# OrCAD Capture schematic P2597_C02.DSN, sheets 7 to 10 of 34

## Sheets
7 27_DC Jack: size Custom
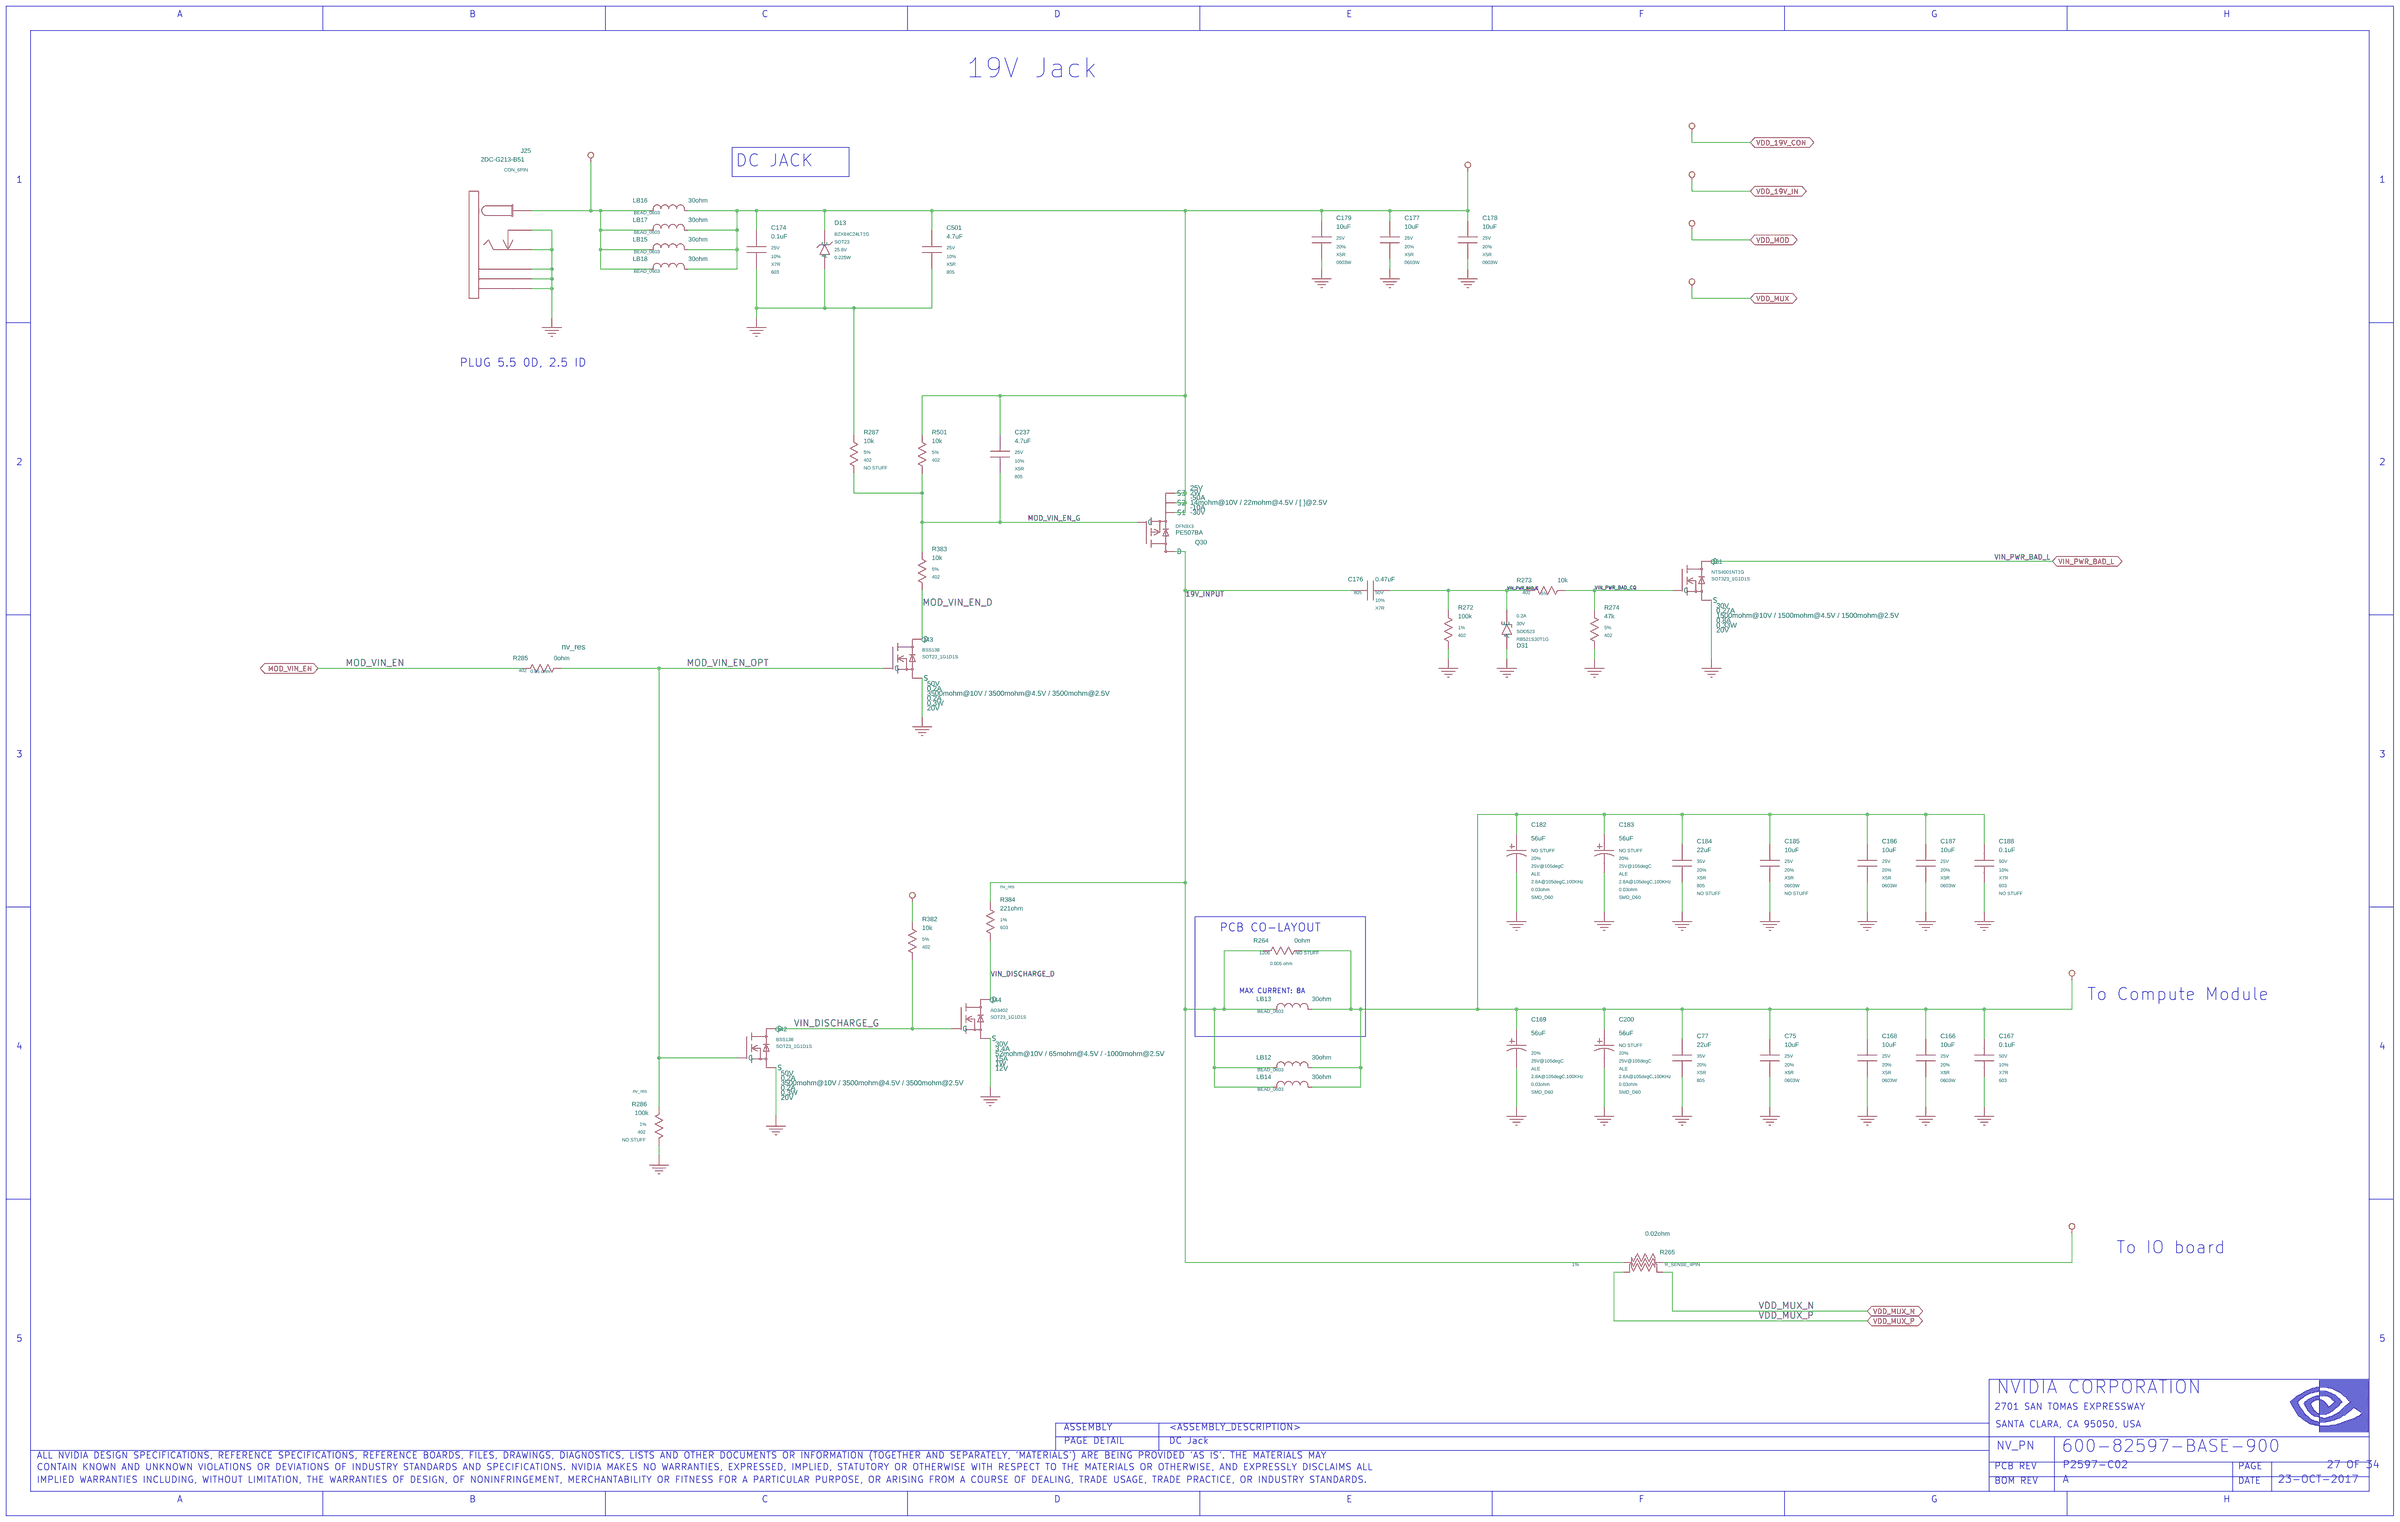
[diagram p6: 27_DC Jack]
8 26_BLANK
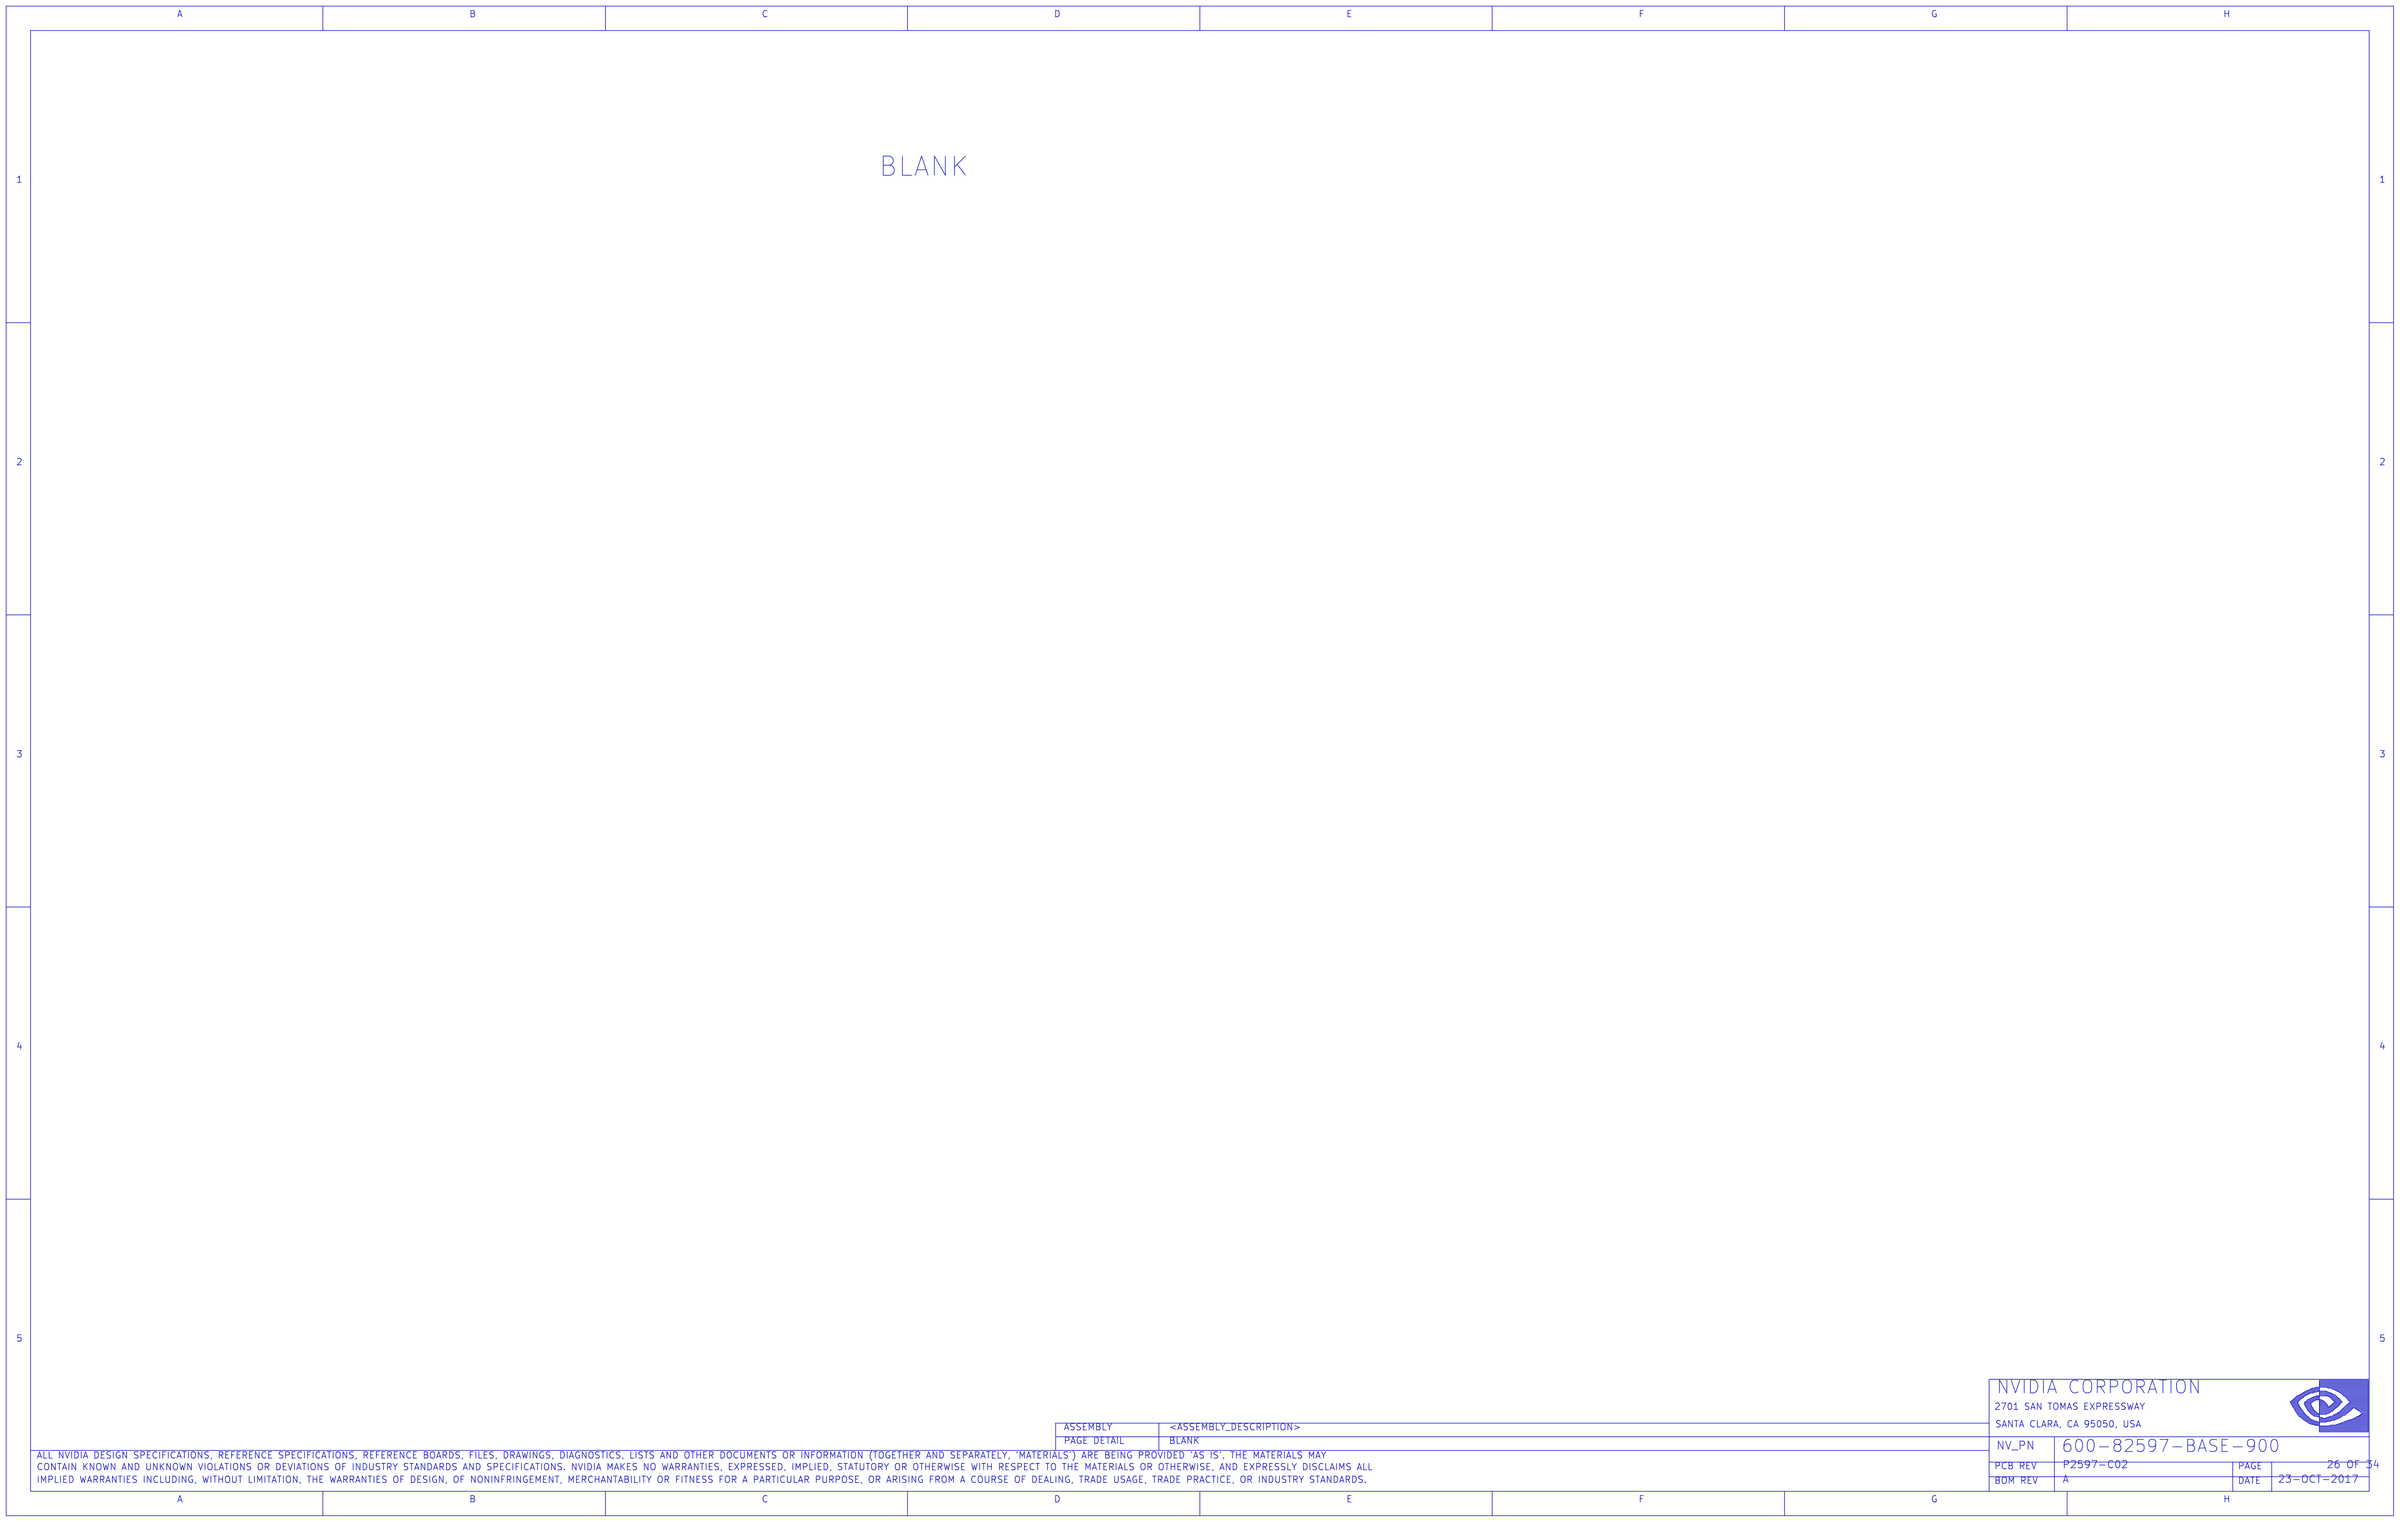
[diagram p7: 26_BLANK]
9 25_Supervisor: size Custom
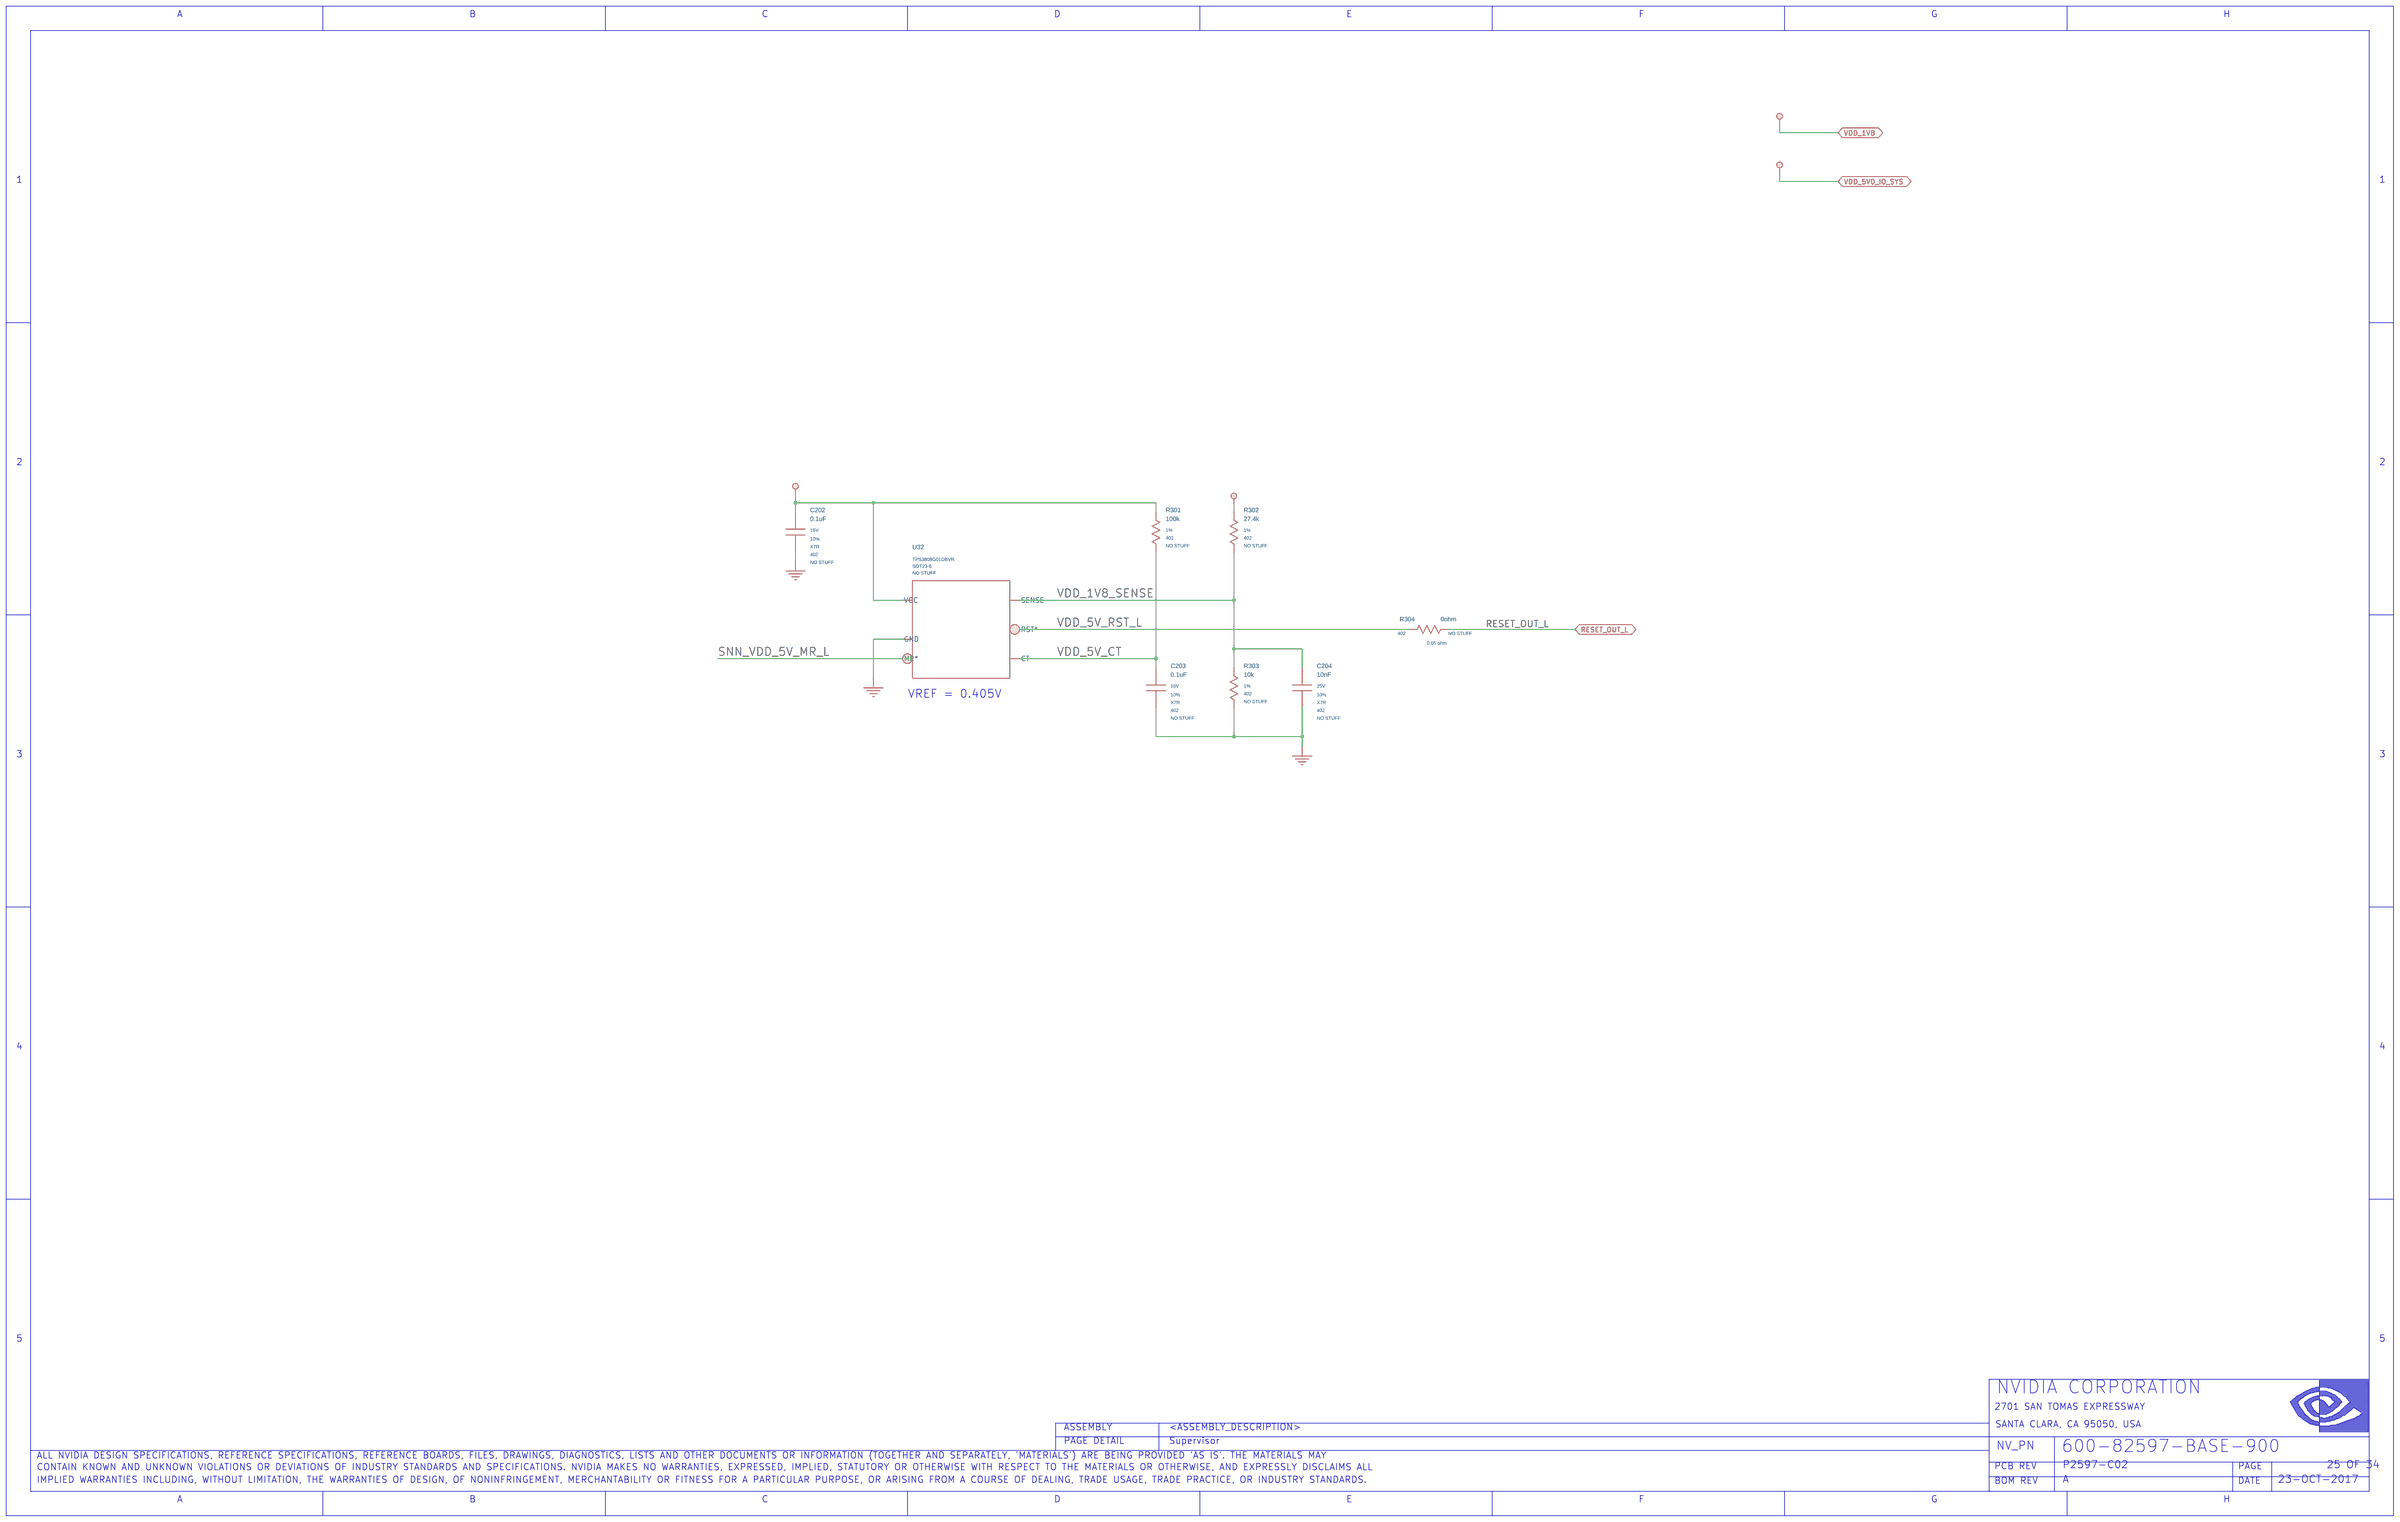
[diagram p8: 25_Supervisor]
10 24_EEPROM: size Custom
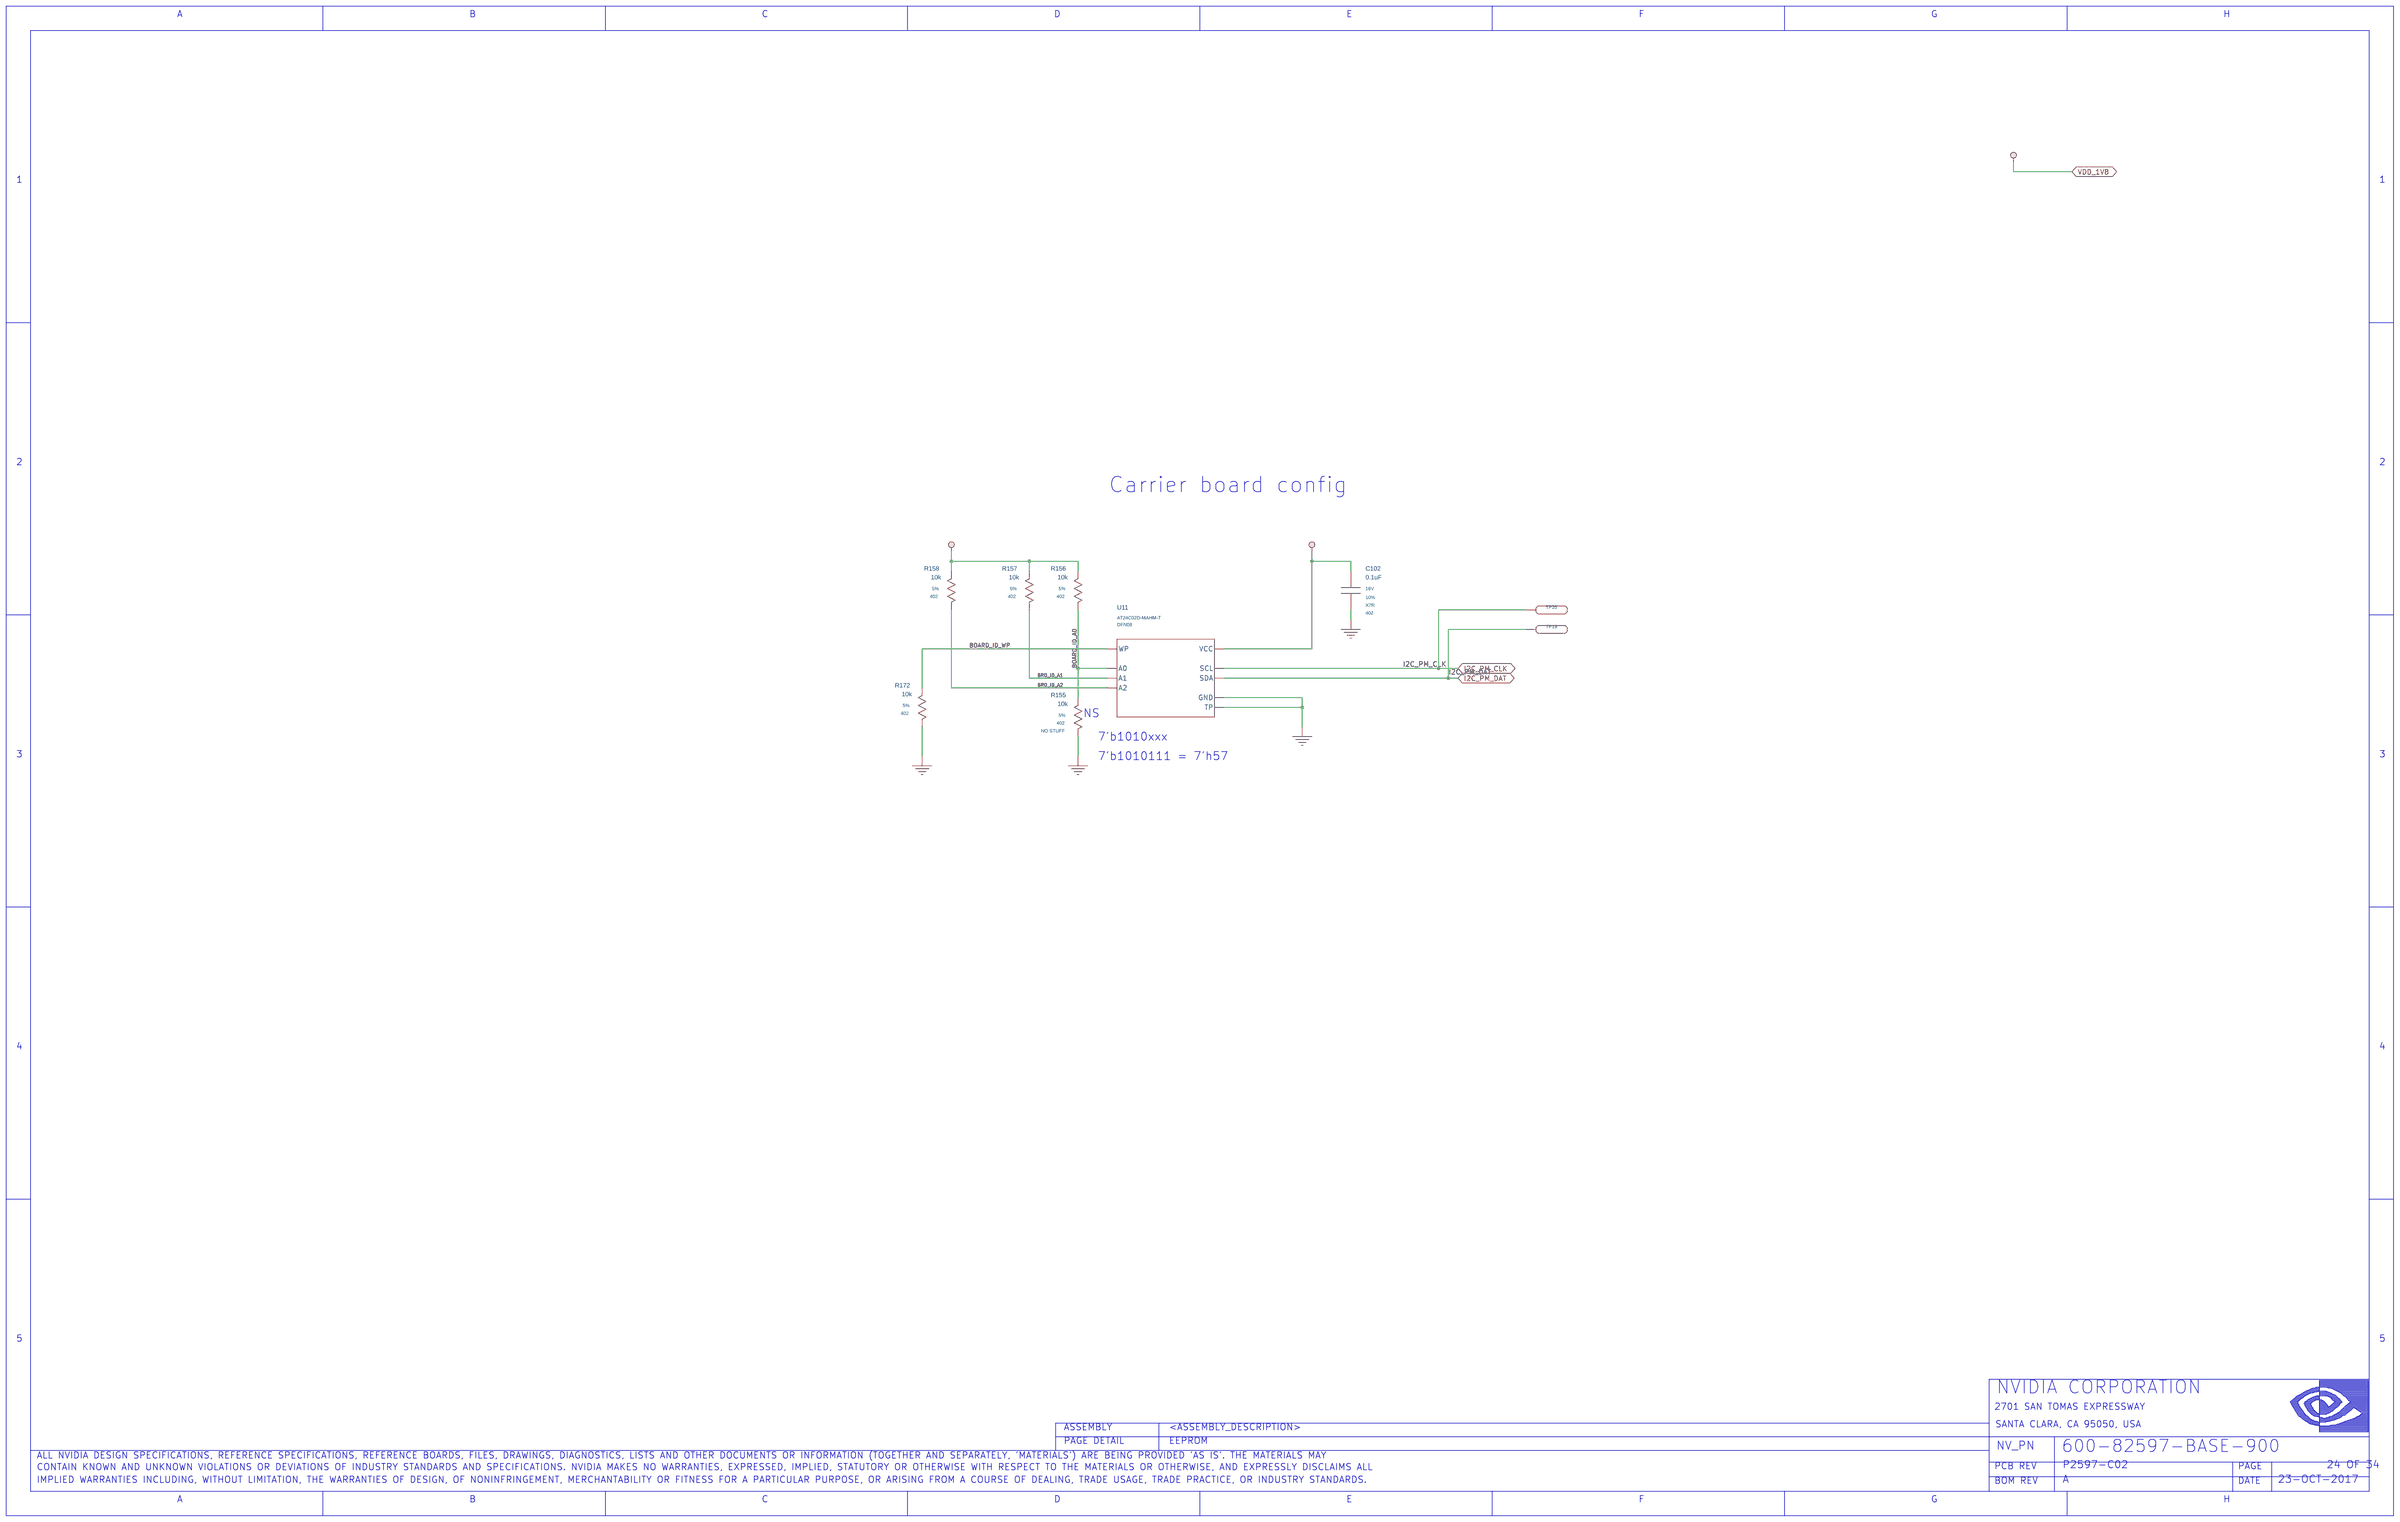
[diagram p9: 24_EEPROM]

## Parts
sheet 24_EEPROM
C102  0.1uF  [402]
R155  10k  [402]
R156  10k  [402]
R157  10k  [402]
R158  10k  [402]
R172  10k  [402]
TP19  LABTESTPOINT  [LTPT28C49P]
TP20  LABTESTPOINT  [LTPT28C49P]
U11  U_MEM_EE_I2C  [DFN08_P050_030X020_T016X016]
sheet 25_Supervisor
C202  0.1uF  [402]
C203  0.1uF  [402]
C204  10nF  [402]
R301  100k  [402]
R302  27.4k  [402]
R303  10k  [402]
R304  0ohm  [402]
U32  U_RST_TPS3808  [SOT23_6]
sheet 27_DC Jack
C75  10uF  [0603_LARGE]
C77  22uF  [805]
C166  10uF  [0603_LARGE]
C167  0.1uF  [603]
C168  10uF  [0603_LARGE]
C169  56uF  [CAP_SMD_066X066]
C174  0.1uF  [603]
C176  0.47uF  [805]
C177  10uF  [0603_LARGE]
C178  10uF  [0603_LARGE]
C179  10uF  [0603_LARGE]
C182  56uF  [CAP_SMD_066X066]
C183  56uF  [CAP_SMD_066X066]
C184  22uF  [805]
C185  10uF  [0603_LARGE]
C186  10uF  [0603_LARGE]
C187  10uF  [0603_LARGE]
C188  0.1uF  [603]
C200  56uF  [CAP_SMD_066X066]
C237  4.7uF  [805]
C501  4.7uF  [805]
D13  D_ZENER  [SOT23]
D31  D_SCHOTTKY  [DIODE_SMD_SOD523_B]
J25  CON_PWR_JACK  [CON_DCPWR_JACK_006_TH_RA_100X130]
LB12  30ohm  [IND_SMD_0603]
LB13  30ohm  [IND_SMD_0603]
LB14  30ohm  [IND_SMD_0603]
LB15  30ohm  [IND_SMD_0603]
LB16  30ohm  [IND_SMD_0603]
LB17  30ohm  [IND_SMD_0603]
LB18  30ohm  [IND_SMD_0603]
Q30  Q_FET_P_ENH  [DFET_SMD_032X033]
Q31  Q_FET_N_ENH  [SOT323]
Q42  Q_FET_N_ENH  [SOT23]
Q43  Q_FET_N_ENH  [SOT23]
Q44  Q_FET_N_ENH  [SOT23]
R264  0ohm  [1206]
R265  0.02ohm  [RES_04_SMD_32X016_B]
R272  100k  [402]
R273  10k  [402]
R274  47k  [402]
R285  0ohm  [402]
R286  100k  [402]
R287  10k  [402]
R382  10k  [402]
R383  10k  [402]
R384  221ohm  [603]
R501  10k  [402]

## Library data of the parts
C102 = C: ASSEMBLY: L4T_EEPROM; CDS_LIB: discrete; CDS_PART_NAME: C_0402-0.1UF,X7R,10%,16V,036-0014-000; CDS_PHYS_PART_NAME: C_0402-0.1UF,X7R,10%,16V,036-0014-000-0.1UF,036-0014-000; CDS_SEC: 1; DEVICE_TYPENAME: C_0402-01UFX7R1016V036-0014-000-01UF036-0014-000; DRAWING: @P2597_C02_LIB.P2597_C02(SCH_1):PAGE24; MAT: X7R; MAX_VOLTAGE: 16V; NV_PN: 036-0014-000; PATH: I34; PHYS_PAGE: 24; ROT: 0; SEC: 1; SIGNAL_MODEL: nv_cap; TOL: 10%; VER: 1; XY: (-5250,4600)
R155 = R#1: ASSEMBLY: L4T_EEPROM; CDS_LIB: discrete; CDS_PART_NAME: R_0402-10K,5 %,62.5MW,195-0486-000; CDS_PHYS_PART_NAME: R_0402-10K,5 %,62.5MW,195-0486-000-10K,195-0486-000; CDS_SEC: 1; CHIPS_PART_NAME: R; DEVICE_TYPENAME: R_0402-10K5625MW195-0486-000-10K195-0486-000; DRAWING: @P2597_C02_LIB.P2597_C02(SCH_1):PAGE24; MAX_WATTAGE: 62.5mW; NV_PN: 195-0486-000; PATH: I43; PHYS_PAGE: 24; ROT: 2; SEC: 1; SIGNAL_MODEL: nv_res; SKU: NO STUFF; TOL: 5%; VER: 2; XY: (-6650,3950)
R156 = R#1: ASSEMBLY: L4T_EEPROM; CDS_LIB: discrete; CDS_PART_NAME: R_0402-10K,5 %,62.5MW,195-0486-000; CDS_PHYS_PART_NAME: R_0402-10K,5 %,62.5MW,195-0486-000-10K,195-0486-000; CDS_SEC: 1; CHIPS_PART_NAME: R; DEVICE_TYPENAME: R_0402-10K5625MW195-0486-000-10K195-0486-000; DRAWING: @P2597_C02_LIB.P2597_C02(SCH_1):PAGE24; MAX_WATTAGE: 62.5mW; NV_PN: 195-0486-000; PATH: I32; PHYS_PAGE: 24; ROT: 2; SEC: 1; SIGNAL_MODEL: nv_res; TOL: 5%; VER: 2; XY: (-6650,4600)
R157 = R#1: ASSEMBLY: L4T_EEPROM; CDS_LIB: discrete; CDS_PART_NAME: R_0402-10K,5 %,62.5MW,195-0486-000; CDS_PHYS_PART_NAME: R_0402-10K,5 %,62.5MW,195-0486-000-10K,195-0486-000; CDS_SEC: 1; CHIPS_PART_NAME: R; DEVICE_TYPENAME: R_0402-10K5625MW195-0486-000-10K195-0486-000; DRAWING: @P2597_C02_LIB.P2597_C02(SCH_1):PAGE24; MAX_WATTAGE: 62.5mW; NV_PN: 195-0486-000; PATH: I31; PHYS_PAGE: 24; ROT: 2; SEC: 1; SIGNAL_MODEL: nv_res; TOL: 5%; VER: 2; XY: (-6900,4600)
R158 = R#1: ASSEMBLY: L4T_EEPROM; CDS_LIB: discrete; CDS_PART_NAME: R_0402-10K,5 %,62.5MW,195-0486-000; CDS_PHYS_PART_NAME: R_0402-10K,5 %,62.5MW,195-0486-000-10K,195-0486-000; CDS_SEC: 1; CHIPS_PART_NAME: R; DEVICE_TYPENAME: R_0402-10K5625MW195-0486-000-10K195-0486-000; DRAWING: @P2597_C02_LIB.P2597_C02(SCH_1):PAGE24; MAX_WATTAGE: 62.5mW; NV_PN: 195-0486-000; PATH: I29; PHYS_PAGE: 24; ROT: 2; SEC: 1; SIGNAL_MODEL: nv_res; TOL: 5%; VER: 2; XY: (-7300,4600)
R172 = R#1: ASSEMBLY: L4T_EEPROM; CDS_LIB: discrete; CDS_PART_NAME: R_0402-10K,5 %,62.5MW,195-0486-000; CDS_PHYS_PART_NAME: R_0402-10K,5 %,62.5MW,195-0486-000-10K,195-0486-000; CDS_SEC: 1; CHIPS_PART_NAME: R; DEVICE_TYPENAME: R_0402-10K5625MW195-0486-000-10K195-0486-000; DRAWING: @P2597_C02_LIB.P2597_C02(SCH_1):PAGE24; MAX_WATTAGE: 62.5mW; NV_PN: 195-0486-000; PATH: I41; PHYS_PAGE: 24; ROT: 2; SEC: 1; SIGNAL_MODEL: nv_res; TOL: 5%; VER: 2; XY: (-7450,4000)
TP19 = LABTESTPOINT: CDS_LIB: electro_mechanic; CDS_PART_NAME: LABTESTPOINT_B28-LABTESTPOINT; CDS_PHYS_PART_NAME: LABTESTPOINT_B28-LABTESTPOINT; CDS_SEC: 1; DEVICE_TYPENAME: LABTESTPOINT_B28-LABTESTPOINT; DRAWING: @P2597_C02_LIB.P2597_C02(SCH_1):PAGE24; PACK_TYPE: B28; PATH: I38; PHYS_PAGE: 24; ROT: 0; SEC: 1; VER: 3; XY: (-4300,4400)
TP20 = LABTESTPOINT: CDS_LIB: electro_mechanic; CDS_PART_NAME: LABTESTPOINT_B28-LABTESTPOINT; CDS_PHYS_PART_NAME: LABTESTPOINT_B28-LABTESTPOINT; CDS_SEC: 1; DEVICE_TYPENAME: LABTESTPOINT_B28-LABTESTPOINT; DRAWING: @P2597_C02_LIB.P2597_C02(SCH_1):PAGE24; PACK_TYPE: B28; PATH: I39; PHYS_PAGE: 24; ROT: 0; SEC: 1; VER: 3; XY: (-4300,4500)
U11 = U_MEM_EE_I2C: ASSEMBLY: L4T_EEPROM; CDS_LIB: memory; CDS_PART_NAME: U_MEM_EE_I2C_DFN08-1MHZ,1.7V..3.6V,AT24C02D-MAHM-T,174-0159-000; CDS_PHYS_PART_NAME: U_MEM_EE_I2C_DFN08-1MHZ,1.7V..3.6V,AT24C02D-MAHM-T,174-0159-000-174-0159-000; CDS_SEC: 1; DEVICE_TYPENAME: U_MEM_EE_I2C_DFN08-1MHZ17V36VAT24C02D-MAHM-T174-0159-000-174-0159-000; DRAWING: @P2597_C02_LIB.P2597_C02(SCH_1):PAGE24; NV_NAME: AT24C02D-MAHM-T; NV_PN: 174-0159-000; PACK_TYPE: DFN08; PATH: I44; PHYS_PAGE: 24; POW: 1.7V..3.6V; ROT: 0; SEC: 1; SEC_TYPE: DFN08; SPEED_GRADE: 1MHz; VER: 2; XY: (-6200,4150)
C202 = C: ASSEMBLY: PWR_MON; CDS_LIB: discrete; CDS_PART_NAME: C_0402-0.1UF,X7R,10%,16V,036-0014-000; CDS_PHYS_PART_NAME: C_0402-0.1UF,X7R,10%,16V,036-0014-000-0.1UF,036-0014-000; CDS_SEC: 1; DEVICE_TYPENAME: C_0402-01UFX7R1016V036-0014-000-01UF036-0014-000; DRAWING: @P2597_C02_LIB.P2597_C02(SCH_1):PAGE25; MAT: X7R; MAX_VOLTAGE: 16V; NV_PN: 036-0014-000; PATH: I2; PHYS_PAGE: 25; ROT: 0; SEC: 1; SIGNAL_MODEL: nv_cap; SKU: NO STUFF; TOL: 10%; VER: 1; XY: (-8100,4900)
C203 = C: ASSEMBLY: PWR_MON; CDS_LIB: discrete; CDS_PART_NAME: C_0402-0.1UF,X7R,10%,16V,036-0014-000; CDS_PHYS_PART_NAME: C_0402-0.1UF,X7R,10%,16V,036-0014-000-0.1UF,036-0014-000; CDS_SEC: 1; DEVICE_TYPENAME: C_0402-01UFX7R1016V036-0014-000-01UF036-0014-000; DRAWING: @P2597_C02_LIB.P2597_C02(SCH_1):PAGE25; MAT: X7R; MAX_VOLTAGE: 16V; NV_PN: 036-0014-000; PATH: I6; PHYS_PAGE: 25; ROT: 0; SEC: 1; SIGNAL_MODEL: nv_cap; SKU: NO STUFF; TOL: 10%; VER: 1; XY: (-6250,4100)
C204 = C: ASSEMBLY: PWR_MON; CDS_LIB: discrete; CDS_PART_NAME: C_0402-10NF,X7R,10%,25V,036-0019-000; CDS_PHYS_PART_NAME: C_0402-10NF,X7R,10%,25V,036-0019-000-036-0019-000,10NF; CDS_SEC: 1; DEVICE_TYPENAME: C_0402-10NFX7R1025V036-0019-000-036-0019-00010NF; DRAWING: @P2597_C02_LIB.P2597_C02(SCH_1):PAGE25; MAT: X7R; MAX_VOLTAGE: 25V; NV_PN: 036-0019-000; PATH: I21; PHYS_PAGE: 25; ROT: 0; SEC: 1; SIGNAL_MODEL: nv_cap; SKU: NO STUFF; TOL: 10%; VER: 1; XY: (-5500,4100)
R301 = R#1: ASSEMBLY: PWR_MON; CDS_LIB: discrete; CDS_PART_NAME: R_0402-100K,1 %,62.5MW,195-0005-000; CDS_PHYS_PART_NAME: R_0402-100K,1 %,62.5MW,195-0005-000-100K,195-0005-000; CDS_SEC: 1; CHIPS_PART_NAME: R; DEVICE_TYPENAME: R_0402-100K1625MW195-0005-000-100K195-0005-000; DRAWING: @P2597_C02_LIB.P2597_C02(SCH_1):PAGE25; MAX_WATTAGE: 62.5mW; NV_PN: 195-0005-000; PATH: I9; PHYS_PAGE: 25; ROT: 0; SEC: 1; SIGNAL_MODEL: nv_res; SKU: NO STUFF; TOL: 1%; VER: 2; XY: (-6250,4900)
R302 = R#1: ASSEMBLY: PWR_MON; CDS_LIB: discrete; CDS_PART_NAME: R_0402-27.4K,1 %,62.5MW,195-0215-000; CDS_PHYS_PART_NAME: R_0402-27.4K,1 %,62.5MW,195-0215-000-195-0215-000,27.4K; CDS_SEC: 1; CHIPS_PART_NAME: R; DEVICE_TYPENAME: R_0402-274K1625MW195-0215-000-195-0215-000274K; DRAWING: @P2597_C02_LIB.P2597_C02(SCH_1):PAGE25; MAX_WATTAGE: 62.5mW; NV_PN: 195-0215-000; PATH: I10; PHYS_PAGE: 25; ROT: 0; SEC: 1; SIGNAL_MODEL: nv_res; SKU: NO STUFF; TOL: 1%; VER: 2; XY: (-5850,4900)
R303 = R#1: ASSEMBLY: PWR_MON; CDS_LIB: discrete; CDS_PART_NAME: R_0402-10K,1 %,62.5MW,195-0004-000; CDS_PHYS_PART_NAME: R_0402-10K,1 %,62.5MW,195-0004-000-10K,195-0004-000; CDS_SEC: 1; CHIPS_PART_NAME: R; DEVICE_TYPENAME: R_0402-10K1625MW195-0004-000-10K195-0004-000; DRAWING: @P2597_C02_LIB.P2597_C02(SCH_1):PAGE25; MAX_WATTAGE: 62.5mW; NV_PN: 195-0004-000; PATH: I20; PHYS_PAGE: 25; ROT: 0; SEC: 1; SIGNAL_MODEL: nv_res; SKU: NO STUFF; TOL: 1%; VER: 2; XY: (-5850,4100)
R304 = R: ASSEMBLY: PWR_MON; CDS_LIB: discrete; CDS_PART_NAME: R_0402-0OHM,0.05 OHM,62.5MW,195-2655-000; CDS_PHYS_PART_NAME: R_0402-0OHM,0.05 OHM,62.5MW,195-2655-000-0OHM,195-2655-000; CDS_SEC: 1; DEVICE_TYPENAME: R_0402-0OHM005OHM625MW195-2655-000-0OHM195-2655-000; DRAWING: @P2597_C02_LIB.P2597_C02(SCH_1):PAGE25; MAX_WATTAGE: 62.5mW; NV_PN: 195-2655-000; PATH: I11; PHYS_PAGE: 25; ROT: 0; SEC: 1; SIGNAL_MODEL: nv_res; SKU: NO STUFF; TOL: 0.05 ohm; VER: 1; XY: (-4850,4400)
U32 = U_RST_TPS3808: ASSEMBLY: PWR_MON; CDS_LIB: digital; CDS_PART_NAME: U_RST_TPS3808_SOT23-6-TPS3808G01DBVR,RESET,115-2045-000; CDS_PHYS_PART_NAME: U_RST_TPS3808_SOT23-6-TPS3808G01DBVR,RESET,115-2045-000-115-2045-000; CDS_SEC: 1; DEVICE_TYPENAME: U_RST_TPS3808_SOT23-6-TPS3808G01DBVRRESET115-2045-000-115-2045-000; DRAWING: @P2597_C02_LIB.P2597_C02(SCH_1):PAGE25; NV_NAME: TPS3808G01DBVR; NV_PN: 115-2045-000; PACK_TYPE: SOT23-6; PATH: I4; PHYS_PAGE: 25; ROT: 0; SEC: 1; SEC_TYPE: SOT23-6; SKU: NO STUFF; TYPE: Reset; VER: 1; XY: (-7250,4400)
C75 = C: ASSEMBLY: CONN_POWER; CDS_LIB: discrete; CDS_PART_NAME: C_0603W-10UF,X5R,20%,25V,032-0186-000; CDS_PHYS_PART_NAME: C_0603W-10UF,X5R,20%,25V,032-0186-000-032-0186-000,10UF; CDS_SEC: 1; DEVICE_TYPENAME: C_0603W-10UFX5R2025V032-0186-000-032-0186-00010UF; DRAWING: @P2597_C02_LIB.P2597_C02(SCH_1):PAGE27; MAT: X5R; MAX_VOLTAGE: 25V; NV_PN: 032-0186-000; PACK_TYPE: 0603W; PATH: I197; PHYS_PAGE: 27; ROT: 0; SEC: 1; SIGNAL_MODEL: nv_cap; TOL: 20%; VER: 1; XY: (-3100,2200)
C77 = C: ASSEMBLY: CONN_POWER; CDS_LIB: discrete; CDS_PART_NAME: C_0805-22UF,X5R,20%,35V,032-0213-000; CDS_PHYS_PART_NAME: C_0805-22UF,X5R,20%,35V,032-0213-000-032-0213-000,22UF; CDS_SEC: 1; DEVICE_TYPENAME: C_0805-22UFX5R2035V032-0213-000-032-0213-00022UF; DRAWING: @P2597_C02_LIB.P2597_C02(SCH_1):PAGE27; MAT: X5R; MAX_VOLTAGE: 35V; NV_PN: 032-0213-000; PATH: I199; PHYS_PAGE: 27; ROT: 0; SEC: 1; SIGNAL_MODEL: nv_cap; TOL: 20%; VER: 1; XY: (-3550,2200)
C166 = C: ASSEMBLY: CONN_POWER; CDS_LIB: discrete; CDS_PART_NAME: C_0603W-10UF,X5R,20%,25V,032-0421-000; CDS_PHYS_PART_NAME: C_0603W-10UF,X5R,20%,25V,032-0421-000-032-0421-000,10UF; CDS_SEC: 1; DEVICE_TYPENAME: C_0603W-10UFX5R2025V032-0421-000-032-0421-00010UF; DRAWING: @P2597_C02_LIB.P2597_C02(SCH_1):PAGE27; MAT: X5R; MAX_VOLTAGE: 25V; NV_PN: 032-0421-000; PACK_TYPE: 0603W; PATH: I241; PHYS_PAGE: 27; ROT: 0; SEC: 1; SIGNAL_MODEL: nv_cap; TOL: 20%; VER: 1; XY: (-2300,2200)
C167 = C: ASSEMBLY: CONN_POWER; CDS_LIB: discrete; CDS_PART_NAME: C_0603-0.1UF,X7R,10%,50V,036-0050-000; CDS_PHYS_PART_NAME: C_0603-0.1UF,X7R,10%,50V,036-0050-000-0.1UF,036-0050-000; CDS_SEC: 1; DEVICE_TYPENAME: C_0603-01UFX7R1050V036-0050-000-01UF036-0050-000; DRAWING: @P2597_C02_LIB.P2597_C02(SCH_1):PAGE27; MAT: X7R; MAX_VOLTAGE: 50V; NV_PN: 036-0050-000; PATH: I242; PHYS_PAGE: 27; ROT: 0; SEC: 1; SIGNAL_MODEL: nv_cap; TOL: 10%; VER: 1; XY: (-2000,2200)
C168 = C: ASSEMBLY: CONN_POWER; CDS_LIB: discrete; CDS_PART_NAME: C_0603W-10UF,X5R,20%,25V,032-0421-000; CDS_PHYS_PART_NAME: C_0603W-10UF,X5R,20%,25V,032-0421-000-032-0421-000,10UF; CDS_SEC: 1; DEVICE_TYPENAME: C_0603W-10UFX5R2025V032-0421-000-032-0421-00010UF; DRAWING: @P2597_C02_LIB.P2597_C02(SCH_1):PAGE27; MAT: X5R; MAX_VOLTAGE: 25V; NV_PN: 032-0421-000; PACK_TYPE: 0603W; PATH: I239; PHYS_PAGE: 27; ROT: 0; SEC: 1; SIGNAL_MODEL: nv_cap; TOL: 20%; VER: 1; XY: (-2600,2200)
C169 = C_POL: ASSEMBLY: CONN_POWER; CDS_LIB: discrete; CDS_PART_NAME: C_POL_SMD_D60-56UF,ALE,20%,25V@105DEGC,0.03OHM,9.999UH,2.8A@105DEGC,100KHZ,032-0240-000; CDS_PHYS_PART_NAME: C_POL_SMD_D60-56UF,ALE,20%,25V@105DEGC,0.03OHM,9.999UH,2.8A@105DEGC,100KHZ,032-0240-000-032-0240-000,56UF; CDS_SEC: 1; DEVICE_TYPENAME: C_POL_SMD_D60-56UFALE2025V105DEGC003OHM9999UH28A105DEGC100KHZ032-0240-000-032-0240-00056UF; DRAWING: @P2597_C02_LIB.P2597_C02(SCH_1):PAGE27; ESL: 9.999uH; ESR: 0.03ohm; MAT: ALE; MAX_VOLTAGE: 25V@105degC; NV_PN: 032-0240-000; PACK_TYPE: SMD_D60; PATH: I237; PHYS_PAGE: 27; RIPPLE_CURRENT: 2.8A@105degC,100KHz; ROT: 0; SEC: 1; SIGNAL_MODEL: nv_capp; TOL: 20%; VER: 1; XY: (-4400,2250)
C174 = C: ASSEMBLY: CONN_POWER; CDS_LIB: discrete; CDS_PART_NAME: C_0603-0.1UF,X7R,10%,25V,036-0043-000; CDS_PHYS_PART_NAME: C_0603-0.1UF,X7R,10%,25V,036-0043-000-0.1UF,036-0043-000; CDS_SEC: 1; DEVICE_TYPENAME: C_0603-01UFX7R1025V036-0043-000-01UF036-0043-000; DRAWING: @P2597_C02_LIB.P2597_C02(SCH_1):PAGE27; MAT: X7R; MAX_VOLTAGE: 25V; NV_PN: 036-0043-000; PATH: I169; PHYS_PAGE: 27; ROT: 0; SEC: 1; SIGNAL_MODEL: DEFAULT_CAPACITOR_100000pF_2_1; TOL: 10%; VER: 1; XY: (-8300,6350)
C176 = C#1: ASSEMBLY: CONN_POWER; CDS_LIB: discrete; CDS_PART_NAME: C_0805-0.47UF,X7R,10%,50V,036-0129-000; CDS_PHYS_PART_NAME: C_0805-0.47UF,X7R,10%,50V,036-0129-000-0.47UF,036-0129-000; CDS_SEC: 1; CHIPS_PART_NAME: C; DEVICE_TYPENAME: C_0805-047UFX7R1050V036-0129-000-047UF036-0129-000; DRAWING: @P2597_C02_LIB.P2597_C02(SCH_1):PAGE27; MAT: X7R; MAX_VOLTAGE: 50V; NV_PN: 036-0129-000; PATH: I210; PHYS_PAGE: 27; ROT: 0; SEC: 1; SIGNAL_MODEL: nv_cap; TOL: 10%; VER: 2; XY: (-5150,4600)
C177 = C: ASSEMBLY: CONN_POWER; CDS_LIB: discrete; CDS_PART_NAME: C_0603W-10UF,X5R,20%,25V,032-0186-000; CDS_PHYS_PART_NAME: C_0603W-10UF,X5R,20%,25V,032-0186-000-032-0186-000,10UF; CDS_SEC: 1; DEVICE_TYPENAME: C_0603W-10UFX5R2025V032-0186-000-032-0186-00010UF; DRAWING: @P2597_C02_LIB.P2597_C02(SCH_1):PAGE27; MAT: X5R; MAX_VOLTAGE: 25V; NV_PN: 032-0186-000; PACK_TYPE: 0603W; PATH: I201; PHYS_PAGE: 27; ROT: 0; SEC: 1; SIGNAL_MODEL: nv_cap; TOL: 20%; VER: 1; XY: (-5050,6400)
C178 = C: ASSEMBLY: CONN_POWER; CDS_LIB: discrete; CDS_PART_NAME: C_0603W-10UF,X5R,20%,25V,032-0186-000; CDS_PHYS_PART_NAME: C_0603W-10UF,X5R,20%,25V,032-0186-000-032-0186-000,10UF; CDS_SEC: 1; DEVICE_TYPENAME: C_0603W-10UFX5R2025V032-0186-000-032-0186-00010UF; DRAWING: @P2597_C02_LIB.P2597_C02(SCH_1):PAGE27; MAT: X5R; MAX_VOLTAGE: 25V; NV_PN: 032-0186-000; PACK_TYPE: 0603W; PATH: I178; PHYS_PAGE: 27; ROT: 0; SEC: 1; SIGNAL_MODEL: nv_cap; TOL: 20%; VER: 1; XY: (-4650,6400)
C179 = C: ASSEMBLY: CONN_POWER; CDS_LIB: discrete; CDS_PART_NAME: C_0603W-10UF,X5R,20%,25V,032-0186-000; CDS_PHYS_PART_NAME: C_0603W-10UF,X5R,20%,25V,032-0186-000-032-0186-000,10UF; CDS_SEC: 1; DEVICE_TYPENAME: C_0603W-10UFX5R2025V032-0186-000-032-0186-00010UF; DRAWING: @P2597_C02_LIB.P2597_C02(SCH_1):PAGE27; MAT: X5R; MAX_VOLTAGE: 25V; NV_PN: 032-0186-000; PACK_TYPE: 0603W; PATH: I204; PHYS_PAGE: 27; ROT: 0; SEC: 1; SIGNAL_MODEL: nv_cap; TOL: 20%; VER: 1; XY: (-5400,6400)
C182 = C_POL: ASSEMBLY: CONN_POWER; CDS_LIB: discrete; CDS_PART_NAME: C_POL_SMD_D60-56UF,ALE,20%,25V@105DEGC,0.03OHM,9.999UH,2.8A@105DEGC,100KHZ,032-0240-000; CDS_PHYS_PART_NAME: C_POL_SMD_D60-56UF,ALE,20%,25V@105DEGC,0.03OHM,9.999UH,2.8A@105DEGC,100KHZ,032-0240-000-032-0240-000,56UF; CDS_SEC: 1; DEVICE_TYPENAME: C_POL_SMD_D60-56UFALE2025V105DEGC003OHM9999UH28A105DEGC100KHZ032-0240-000-032-0240-00056UF; DRAWING: @P2597_C02_LIB.P2597_C02(SCH_1):PAGE27; ESL: 9.999uH; ESR: 0.03ohm; MAT: ALE; MAX_VOLTAGE: 25V@105degC; NV_PN: 032-0240-000; PACK_TYPE: SMD_D60; PATH: I293; PHYS_PAGE: 27; RIPPLE_CURRENT: 2.8A@105degC,100KHz; ROT: 0; SEC: 1; SIGNAL_MODEL: nv_capp; SKU: NO STUFF; TOL: 20%; VER: 1; XY: (-4400,3250)
C183 = C_POL: ASSEMBLY: CONN_POWER; CDS_LIB: discrete; CDS_PART_NAME: C_POL_SMD_D60-56UF,ALE,20%,25V@105DEGC,0.03OHM,9.999UH,2.8A@105DEGC,100KHZ,032-0240-000; CDS_PHYS_PART_NAME: C_POL_SMD_D60-56UF,ALE,20%,25V@105DEGC,0.03OHM,9.999UH,2.8A@105DEGC,100KHZ,032-0240-000-032-0240-000,56UF; CDS_SEC: 1; DEVICE_TYPENAME: C_POL_SMD_D60-56UFALE2025V105DEGC003OHM9999UH28A105DEGC100KHZ032-0240-000-032-0240-00056UF; DRAWING: @P2597_C02_LIB.P2597_C02(SCH_1):PAGE27; ESL: 9.999uH; ESR: 0.03ohm; MAT: ALE; MAX_VOLTAGE: 25V@105degC; NV_PN: 032-0240-000; PACK_TYPE: SMD_D60; PATH: I286; PHYS_PAGE: 27; RIPPLE_CURRENT: 2.8A@105degC,100KHz; ROT: 0; SEC: 1; SIGNAL_MODEL: nv_capp; SKU: NO STUFF; TOL: 20%; VER: 1; XY: (-3950,3250)
C184 = C: ASSEMBLY: CONN_POWER; CDS_LIB: discrete; CDS_PART_NAME: C_0805-22UF,X5R,20%,35V,032-0213-000; CDS_PHYS_PART_NAME: C_0805-22UF,X5R,20%,35V,032-0213-000-032-0213-000,22UF; CDS_SEC: 1; DEVICE_TYPENAME: C_0805-22UFX5R2035V032-0213-000-032-0213-00022UF; DRAWING: @P2597_C02_LIB.P2597_C02(SCH_1):PAGE27; MAT: X5R; MAX_VOLTAGE: 35V; NV_PN: 032-0213-000; PATH: I285; PHYS_PAGE: 27; ROT: 0; SEC: 1; SIGNAL_MODEL: nv_cap; SKU: NO STUFF; TOL: 20%; VER: 1; XY: (-3550,3200)
C185 = C: ASSEMBLY: CONN_POWER; CDS_LIB: discrete; CDS_PART_NAME: C_0603W-10UF,X5R,20%,25V,032-0186-000; CDS_PHYS_PART_NAME: C_0603W-10UF,X5R,20%,25V,032-0186-000-032-0186-000,10UF; CDS_SEC: 1; DEVICE_TYPENAME: C_0603W-10UFX5R2025V032-0186-000-032-0186-00010UF; DRAWING: @P2597_C02_LIB.P2597_C02(SCH_1):PAGE27; MAT: X5R; MAX_VOLTAGE: 25V; NV_PN: 032-0186-000; PACK_TYPE: 0603W; PATH: I284; PHYS_PAGE: 27; ROT: 0; SEC: 1; SIGNAL_MODEL: nv_cap; SKU: NO STUFF; TOL: 20%; VER: 1; XY: (-3100,3200)
C186 = C: ASSEMBLY: CONN_POWER; CDS_LIB: discrete; CDS_PART_NAME: C_0603W-10UF,X5R,20%,25V,032-0421-000; CDS_PHYS_PART_NAME: C_0603W-10UF,X5R,20%,25V,032-0421-000-032-0421-000,10UF; CDS_SEC: 1; DEVICE_TYPENAME: C_0603W-10UFX5R2025V032-0421-000-032-0421-00010UF; DRAWING: @P2597_C02_LIB.P2597_C02(SCH_1):PAGE27; MAT: X5R; MAX_VOLTAGE: 25V; NV_PN: 032-0421-000; PACK_TYPE: 0603W; PATH: I283; PHYS_PAGE: 27; ROT: 0; SEC: 1; SIGNAL_MODEL: nv_cap; TOL: 20%; VER: 1; XY: (-2600,3200)
C187 = C: ASSEMBLY: CONN_POWER; CDS_LIB: discrete; CDS_PART_NAME: C_0603W-10UF,X5R,20%,25V,032-0421-000; CDS_PHYS_PART_NAME: C_0603W-10UF,X5R,20%,25V,032-0421-000-032-0421-000,10UF; CDS_SEC: 1; DEVICE_TYPENAME: C_0603W-10UFX5R2025V032-0421-000-032-0421-00010UF; DRAWING: @P2597_C02_LIB.P2597_C02(SCH_1):PAGE27; MAT: X5R; MAX_VOLTAGE: 25V; NV_PN: 032-0421-000; PACK_TYPE: 0603W; PATH: I288; PHYS_PAGE: 27; ROT: 0; SEC: 1; SIGNAL_MODEL: nv_cap; TOL: 20%; VER: 1; XY: (-2300,3200)
C188 = C: ASSEMBLY: CONN_POWER; CDS_LIB: discrete; CDS_PART_NAME: C_0603-0.1UF,X7R,10%,50V,036-0050-000; CDS_PHYS_PART_NAME: C_0603-0.1UF,X7R,10%,50V,036-0050-000-0.1UF,036-0050-000; CDS_SEC: 1; DEVICE_TYPENAME: C_0603-01UFX7R1050V036-0050-000-01UF036-0050-000; DRAWING: @P2597_C02_LIB.P2597_C02(SCH_1):PAGE27; MAT: X7R; MAX_VOLTAGE: 50V; NV_PN: 036-0050-000; PATH: I287; PHYS_PAGE: 27; ROT: 0; SEC: 1; SIGNAL_MODEL: nv_cap; SKU: NO STUFF; TOL: 10%; VER: 1; XY: (-2000,3200)
C200 = C_POL: ASSEMBLY: CONN_POWER; CDS_LIB: discrete; CDS_PART_NAME: C_POL_SMD_D60-56UF,ALE,20%,25V@105DEGC,0.03OHM,9.999UH,2.8A@105DEGC,100KHZ,032-0240-000; CDS_PHYS_PART_NAME: C_POL_SMD_D60-56UF,ALE,20%,25V@105DEGC,0.03OHM,9.999UH,2.8A@105DEGC,100KHZ,032-0240-000-032-0240-000,56UF; CDS_SEC: 1; DEVICE_TYPENAME: C_POL_SMD_D60-56UFALE2025V105DEGC003OHM9999UH28A105DEGC100KHZ032-0240-000-032-0240-00056UF; DRAWING: @P2597_C02_LIB.P2597_C02(SCH_1):PAGE27; ESL: 9.999uH; ESR: 0.03ohm; MAT: ALE; MAX_VOLTAGE: 25V@105degC; NV_PN: 032-0240-000; PACK_TYPE: SMD_D60; PATH: I257; PHYS_PAGE: 27; RIPPLE_CURRENT: 2.8A@105degC,100KHz; ROT: 0; SEC: 1; SIGNAL_MODEL: nv_capp; SKU: NO STUFF; TOL: 20%; VER: 1; XY: (-3950,2250)
C237 = C: ASSEMBLY: CONN_POWER; CDS_LIB: discrete; CDS_PART_NAME: C_0805-4.7UF,X5R,10%,25V,039-0205-000; CDS_PHYS_PART_NAME: C_0805-4.7UF,X5R,10%,25V,039-0205-000-039-0205-000,4.7UF; CDS_SEC: 1; DEVICE_TYPENAME: C_0805-47UFX5R1025V039-0205-000-039-0205-00047UF; DRAWING: @P2597_C02_LIB.P2597_C02(SCH_1):PAGE27; MAT: X5R; MAX_VOLTAGE: 25V; NV_PN: 039-0205-000; PATH: I263; PHYS_PAGE: 27; ROT: 0; SEC: 1; SIGNAL_MODEL: DEFAULT_CAPACITOR_4.7e+06pF_2_1; TOL: 10%; VER: 1; XY: (-7050,5300)
C501 = C: ASSEMBLY: CONN_POWER; CDS_LIB: discrete; CDS_PART_NAME: C_0805-4.7UF,X5R,10%,25V,039-0205-000; CDS_PHYS_PART_NAME: C_0805-4.7UF,X5R,10%,25V,039-0205-000-039-0205-000,4.7UF; CDS_SEC: 1; DEVICE_TYPENAME: C_0805-47UFX5R1025V039-0205-000-039-0205-00047UF; DRAWING: @P2597_C02_LIB.P2597_C02(SCH_1):PAGE27; MAT: X5R; MAX_VOLTAGE: 25V; NV_PN: 039-0205-000; PATH: I172; PHYS_PAGE: 27; ROT: 0; SEC: 1; SIGNAL_MODEL: DEFAULT_CAPACITOR_4.7e+06pF_2_1; TOL: 10%; VER: 1; XY: (-7400,6350)
D13 = D_ZENER: ASSEMBLY: CONN_POWER; CDS_LIB: discrete; CDS_PART_NAME: D_ZENER_SOT23-BZX84C24LT1G,25.6V,9999A,0.9V@10MA,0.225W,090-0178-000; CDS_PHYS_PART_NAME: D_ZENER_SOT23-BZX84C24LT1G,25.6V,9999A,0.9V@10MA,0.225W,090-0178-000-090-0178-000; CDS_SEC: 1; CONTINUOUS_CURRENT: 0.225W; DEVICE_TYPENAME: D_ZENER_SOT23-BZX84C24LT1G256V9999A09V10MA0225W090-0178-000-090-0178-000; DRAWING: @P2597_C02_LIB.P2597_C02(SCH_1):PAGE27; FORWARD_VOLTAGE: 0.9V@10mA; MAX_CURRENT: 9999A; MAX_VOLTAGE: 25.6V; NV_NAME: BZX84C24LT1G; NV_PN: 090-0178-000; PATH: I170; PHYS_PAGE: 27; ROT: 0; SEC: 1; VER: 2; XY: (-7950,6350)
D31 = D_SCHOTTKY#1: ASSEMBLY: CONN_POWER; CDS_LIB: discrete; CDS_PART_NAME: D_SCHOTTKY_SOD523-RB521S30T1G,SINGLE,30V,1A,0.5V@0.2A,0.2A,090-0102-000; CDS_PHYS_PART_NAME: D_SCHOTTKY_SOD523-RB521S30T1G,SINGLE,30V,1A,0.5V@0.2A,0.2A,090-0102-000-090-0102-000; CDS_SEC: 1; CONFIGURATION: Single; CONTINUOUS_CURRENT: 0.2A; DEVICE_TYPENAME: D_SCHOTTKY_SOD523-RB521S30T1GSINGLE30V1A05V02A02A090-0102-000-090-0102-000; DRAWING: @P2597_C02_LIB.P2597_C02(SCH_1):PAGE27; FORWARD_VOLTAGE: 0.5V@0.2A; MAX_CURRENT: 1A; MAX_VOLTAGE: 30V; NV_NAME: RB521S30T1G; NV_PN: 090-0102-000; PACK_TYPE: SOD523; PATH: I258; PHYS_PAGE: 27; ROT: 6; SEC: 1; VER: 2; XY: (-4450,4400)
J25 = CON_PWR_JACK: ANGLE: 90; ASSEMBLY: CONN_POWER; CDS_LIB: electro_mechanic; CDS_PART_NAME: CON_PWR_JACK_CON_6PIN-2DC-G213-B51,FEMALE,4.7MM,90,YES,NO,YES,NO,NO,20V,10A,065-0400-000; CDS_PHYS_PART_NAME: CON_PWR_JACK_CON_6PIN-2DC-G213-B51,FEMALE,4.7MM,90,YES,NO,YES,NO,NO,20V,10A,065-0400-000-065-0400-000; CDS_SEC: 1; DEVICE_TYPENAME: CON_PWR_JACK_CON_6PIN-2DC-G213-B51FEMALE47MM90YESNOYESNONO20V10A065-0400-000-065-0400-000; DRAWING: @P2597_C02_LIB.P2597_C02(SCH_1):PAGE27; EMI_GROUND_TAB: NO; GENDER: Female; LATCHING: YES; MAX_CURRENT: 10A; MAX_VOLTAGE: 20V; NV_NAME: 2DC-G213-B51; NV_PN: 065-0400-000; PACK_TYPE: CON_6PIN; PATH: I220; PHYS_PAGE: 27; PITCH: 4.7mm; REFLOW: YES; ROT: 2; SEC: 1; SEC_TYPE: CON_6PIN; SHIELDED: No; SHROUDED: No; VER: 4; XY: (-9750,6550)
LB12 = L: ACOUSTIC_MARGIN: N/A; ASSEMBLY: CONN_POWER; CDS_LIB: discrete; CDS_PART_NAME: L_BEAD_0603-30OHM,FERRITE,33.33%,[ ],5A,0.01OHM,[ ],N/A,N/A,100-0026-000; CDS_PHYS_PART_NAME: L_BEAD_0603-30OHM,FERRITE,33.33%,[ ],5A,0.01OHM,[ ],N/A,N/A,100-0026-000-100-0026-000,30OHM; CDS_SEC: 1; CONTINUOUS_CURRENT: [ ]; DC_RESISTANCE: 0.01ohm; DEVICE_TYPENAME: L_BEAD_0603-30OHMFERRITE33335A001OHMNANA100-0026-000-100-0026-00030OHM; DRAWING: @P2597_C02_LIB.P2597_C02(SCH_1):PAGE27; MAT: Ferrite; MAX_CURRENT: 5A; NV_PN: 100-0026-000; PACK_TYPE: BEAD_0603; PATH: I187; PHYS_PAGE: 27; Q: [ ]; ROT: 0; SEC: 1; SELF_RESONANCE_FREQ: N/A; SIGNAL_MODEL: nv_ind_noxnet; TOL: 33.33%; VER: 1; XY: (-5550,2150)
LB13 = L: ACOUSTIC_MARGIN: N/A; ASSEMBLY: CONN_POWER; CDS_LIB: discrete; CDS_PART_NAME: L_BEAD_0603-30OHM,FERRITE,33.33%,[ ],5A,0.01OHM,[ ],N/A,N/A,100-0026-000; CDS_PHYS_PART_NAME: L_BEAD_0603-30OHM,FERRITE,33.33%,[ ],5A,0.01OHM,[ ],N/A,N/A,100-0026-000-100-0026-000,30OHM; CDS_SEC: 1; CONTINUOUS_CURRENT: [ ]; DC_RESISTANCE: 0.01ohm; DEVICE_TYPENAME: L_BEAD_0603-30OHMFERRITE33335A001OHMNANA100-0026-000-100-0026-00030OHM; DRAWING: @P2597_C02_LIB.P2597_C02(SCH_1):PAGE27; MAT: Ferrite; MAX_CURRENT: 5A; NV_PN: 100-0026-000; PACK_TYPE: BEAD_0603; PATH: I188; PHYS_PAGE: 27; PLACEMENT_NOTE: CoLayout with R264; Q: [ ]; ROT: 0; SEC: 1; SELF_RESONANCE_FREQ: N/A; SIGNAL_MODEL: nv_ind_noxnet; TOL: 33.33%; VER: 1; XY: (-5550,2450)
LB14 = L: ACOUSTIC_MARGIN: N/A; ASSEMBLY: CONN_POWER; CDS_LIB: discrete; CDS_PART_NAME: L_BEAD_0603-30OHM,FERRITE,33.33%,[ ],5A,0.01OHM,[ ],N/A,N/A,100-0026-000; CDS_PHYS_PART_NAME: L_BEAD_0603-30OHM,FERRITE,33.33%,[ ],5A,0.01OHM,[ ],N/A,N/A,100-0026-000-100-0026-000,30OHM; CDS_SEC: 1; CONTINUOUS_CURRENT: [ ]; DC_RESISTANCE: 0.01ohm; DEVICE_TYPENAME: L_BEAD_0603-30OHMFERRITE33335A001OHMNANA100-0026-000-100-0026-00030OHM; DRAWING: @P2597_C02_LIB.P2597_C02(SCH_1):PAGE27; MAT: Ferrite; MAX_CURRENT: 5A; NV_PN: 100-0026-000; PACK_TYPE: BEAD_0603; PATH: I223; PHYS_PAGE: 27; Q: [ ]; ROT: 0; SEC: 1; SELF_RESONANCE_FREQ: N/A; SIGNAL_MODEL: nv_ind_noxnet; TOL: 33.33%; VER: 1; XY: (-5550,2050)
LB15 = L: ACOUSTIC_MARGIN: N/A; ASSEMBLY: CONN_POWER; CDS_LIB: discrete; CDS_PART_NAME: L_BEAD_0603-30OHM,FERRITE,33.33%,[ ],5A,0.01OHM,[ ],N/A,N/A,100-0026-000; CDS_PHYS_PART_NAME: L_BEAD_0603-30OHM,FERRITE,33.33%,[ ],5A,0.01OHM,[ ],N/A,N/A,100-0026-000-100-0026-000,30OHM; CDS_SEC: 1; CONTINUOUS_CURRENT: [ ]; DC_RESISTANCE: 0.01ohm; DEVICE_TYPENAME: L_BEAD_0603-30OHMFERRITE33335A001OHMNANA100-0026-000-100-0026-00030OHM; DRAWING: @P2597_C02_LIB.P2597_C02(SCH_1):PAGE27; MAT: Ferrite; MAX_CURRENT: 5A; NV_PN: 100-0026-000; PACK_TYPE: BEAD_0603; PATH: I221; PHYS_PAGE: 27; Q: [ ]; ROT: 0; SEC: 1; SELF_RESONANCE_FREQ: N/A; SIGNAL_MODEL: nv_ind_noxnet; TOL: 33.33%; VER: 1; XY: (-8750,6350)
LB16 = L: ACOUSTIC_MARGIN: N/A; ASSEMBLY: CONN_POWER; CDS_LIB: discrete; CDS_PART_NAME: L_BEAD_0603-30OHM,FERRITE,33.33%,[ ],5A,0.01OHM,[ ],N/A,N/A,100-0026-000; CDS_PHYS_PART_NAME: L_BEAD_0603-30OHM,FERRITE,33.33%,[ ],5A,0.01OHM,[ ],N/A,N/A,100-0026-000-100-0026-000,30OHM; CDS_SEC: 1; CONTINUOUS_CURRENT: [ ]; DC_RESISTANCE: 0.01ohm; DEVICE_TYPENAME: L_BEAD_0603-30OHMFERRITE33335A001OHMNANA100-0026-000-100-0026-00030OHM; DRAWING: @P2597_C02_LIB.P2597_C02(SCH_1):PAGE27; MAT: Ferrite; MAX_CURRENT: 5A; NV_PN: 100-0026-000; PACK_TYPE: BEAD_0603; PATH: I167; PHYS_PAGE: 27; Q: [ ]; ROT: 0; SEC: 1; SELF_RESONANCE_FREQ: N/A; SIGNAL_MODEL: nv_ind_noxnet; TOL: 33.33%; VER: 1; XY: (-8750,6550)
LB17 = L: ACOUSTIC_MARGIN: N/A; ASSEMBLY: CONN_POWER; CDS_LIB: discrete; CDS_PART_NAME: L_BEAD_0603-30OHM,FERRITE,33.33%,[ ],5A,0.01OHM,[ ],N/A,N/A,100-0026-000; CDS_PHYS_PART_NAME: L_BEAD_0603-30OHM,FERRITE,33.33%,[ ],5A,0.01OHM,[ ],N/A,N/A,100-0026-000-100-0026-000,30OHM; CDS_SEC: 1; CONTINUOUS_CURRENT: [ ]; DC_RESISTANCE: 0.01ohm; DEVICE_TYPENAME: L_BEAD_0603-30OHMFERRITE33335A001OHMNANA100-0026-000-100-0026-00030OHM; DRAWING: @P2597_C02_LIB.P2597_C02(SCH_1):PAGE27; MAT: Ferrite; MAX_CURRENT: 5A; NV_PN: 100-0026-000; PACK_TYPE: BEAD_0603; PATH: I166; PHYS_PAGE: 27; Q: [ ]; ROT: 0; SEC: 1; SELF_RESONANCE_FREQ: N/A; SIGNAL_MODEL: nv_ind_noxnet; TOL: 33.33%; VER: 1; XY: (-8750,6450)
LB18 = L: ACOUSTIC_MARGIN: N/A; ASSEMBLY: CONN_POWER; CDS_LIB: discrete; CDS_PART_NAME: L_BEAD_0603-30OHM,FERRITE,33.33%,[ ],5A,0.01OHM,[ ],N/A,N/A,100-0026-000; CDS_PHYS_PART_NAME: L_BEAD_0603-30OHM,FERRITE,33.33%,[ ],5A,0.01OHM,[ ],N/A,N/A,100-0026-000-100-0026-000,30OHM; CDS_SEC: 1; CONTINUOUS_CURRENT: [ ]; DC_RESISTANCE: 0.01ohm; DEVICE_TYPENAME: L_BEAD_0603-30OHMFERRITE33335A001OHMNANA100-0026-000-100-0026-00030OHM; DRAWING: @P2597_C02_LIB.P2597_C02(SCH_1):PAGE27; MAT: Ferrite; MAX_CURRENT: 5A; NV_PN: 100-0026-000; PACK_TYPE: BEAD_0603; PATH: I222; PHYS_PAGE: 27; Q: [ ]; ROT: 0; SEC: 1; SELF_RESONANCE_FREQ: N/A; SIGNAL_MODEL: nv_ind_noxnet; TOL: 33.33%; VER: 1; XY: (-8750,6250)
Q30 = Q_FET_P_ENH#1: ASSEMBLY: CONN_POWER; CDS_LIB: discrete; CDS_PART_NAME: Q_FET_P_ENH_DFN3X3-PE507BA,-30V,14MOHM@10V / 22MOHM@4.5V / [ ]@2.5V,-10A,-50A,25V,2W,49.1NC@10V / 0NC@4.5V / [ ]@2.5V,300-1028A; CDS_PHYS_PART_NAME: Q_FET_P_ENH_DFN3X3-PE507BA,-30V,14MOHM@10V / 22MOHM@4.5V / [ ]@2.5V,-10A,-50A,25V,2W,49.1NC@10V / 0NC@4.5V / [ ]@2.5V,300-1028B; CDS_SEC: 1; CONTINUOUS_CURRENT: -10A; DEVICE_TYPENAME: Q_FET_P_ENH_DFN3X3-PE507BA-30V14MOHM10V22MOHM45V25V-10A-50A25V2W491NC10V0NC45V25V300-1028B; DRAWING: @P2597_C02_LIB.P2597_C02(SCH_1):PAGE27; MAX_CURRENT: -50A; MAX_VOLTAGE: -30V; MAX_WATTAGE: 2W; NV_NAME: PE507BA; NV_PN: 300-1028-000; PACK_TYPE: DFN3X3; PATH: I224; PHYS_PAGE: 27; Q_G: 49.1nC@10V / 0nC@4.5V / [ ]@2.5V; ROT: 6; R_DS_ON: 14mohm@10V / 22mohm@4.5V / [ ]@2.5V; SEC: 1; SEC_TYPE: DFN3X3; VER: 8; V_BE_GS: 25V; XY: (-6250,4900)
Q31 = Q_FET_N_ENH#2: ASSEMBLY: CONN_POWER; CDS_LIB: discrete; CDS_PART_NAME: Q_FET_N_ENH_SOT323_1G1D1S-NTS4001NT1G,30V,1500MOHM@10V / 1500MOHM@4.5V / 1500MOHM@2.5V,0.27A,0.8A,20V,0.33W,[ ]@10V / [ ]@4.5VA; CDS_PHYS_PART_NAME: Q_FET_N_ENH_SOT323_1G1D1S-NTS4001NT1G,30V,1500MOHM@10V / 1500MOHM@4.5V / 1500MOHM@2.5V,0.27A,0.8A,20V,0.33W,[ ]@10V / [ ]@4.5VB; CDS_SEC: 1; CONTINUOUS_CURRENT: 0.27A; CaptureCellPackProp: Q_FET_N_ENH__sym_2##2; DEVICE_TYPENAME: Q_FET_N_ENH_SOT323_1G1D1S-NTS4001NT1G30V1500MOHM10V1500MOHM45V1500MOHM25V027A08A20V033W10V45VB; DRAWING: @P2597_C02_LIB.P2597_C02(SCH_1):PAGE27; MAX_CURRENT: 0.8A; MAX_VOLTAGE: 30V; MAX_WATTAGE: 0.33W; NV_NAME: NTS4001NT1G; NV_PN: 300-0485-000; PACK_TYPE: SOT323_1G1D1S; PATH: I216; PHYS_PAGE: 27; Q_G: [ ]@10V / [ ]@4.5V / [ ]@2.5V; ROT: 0; R_DS_ON: 1500mohm@10V / 1500mohm@4.5V / 1500mohm@2.5V; SEC: 1; SEC_TYPE: SOT323_1G1D1S; VER: 2; V_BE_GS: 20V; XY: (-3500,4650)
Q42 = Q_FET_N_ENH#2: ASSEMBLY: CONN_POWER; CDS_LIB: discrete; CDS_PART_NAME: Q_FET_N_ENH_SOT23_1G1D1S-BSS138,50V,3500MOHM@10V / 3500MOHM@4.5V / 3500MOHM@2.5V,0.2A,0.2A,20V,0.3W,[ ]@10V / [ ]@4.5V / [ ]@2A; CDS_PHYS_PART_NAME: Q_FET_N_ENH_SOT23_1G1D1S-BSS138,50V,3500MOHM@10V / 3500MOHM@4.5V / 3500MOHM@2.5V,0.2A,0.2A,20V,0.3W,[ ]@10V / [ ]@4.5V / [ ]@2B; CDS_SEC: 1; CONTINUOUS_CURRENT: 0.2A; CaptureCellPackProp: Q_FET_N_ENH__sym_2##2; DEVICE_TYPENAME: Q_FET_N_ENH_SOT23_1G1D1S-BSS13850V3500MOHM10V3500MOHM45V3500MOHM25V02A02A20V03W10V45V2B; DRAWING: @P2597_C02_LIB.P2597_C02(SCH_1):PAGE27; MAX_CURRENT: 0.2A; MAX_VOLTAGE: 50V; MAX_WATTAGE: 0.3W; NV_NAME: BSS138; NV_PN: 300-0156-000; PACK_TYPE: SOT23_1G1D1S; PATH: I278; PHYS_PAGE: 27; Q_G: [ ]@10V / [ ]@4.5V / [ ]@2.5V; ROT: 0; R_DS_ON: 3500mohm@10V / 3500mohm@4.5V / 3500mohm@2.5V; SEC: 1; VER: 2; V_BE_GS: 20V; XY: (-8300,2250)
Q43 = Q_FET_N_ENH#2: ASSEMBLY: CONN_POWER; CDS_LIB: discrete; CDS_PART_NAME: Q_FET_N_ENH_SOT23_1G1D1S-BSS138,50V,3500MOHM@10V / 3500MOHM@4.5V / 3500MOHM@2.5V,0.2A,0.2A,20V,0.3W,[ ]@10V / [ ]@4.5V / [ ]@2A; CDS_PHYS_PART_NAME: Q_FET_N_ENH_SOT23_1G1D1S-BSS138,50V,3500MOHM@10V / 3500MOHM@4.5V / 3500MOHM@2.5V,0.2A,0.2A,20V,0.3W,[ ]@10V / [ ]@4.5V / [ ]@2B; CDS_SEC: 1; CONTINUOUS_CURRENT: 0.2A; CaptureCellPackProp: Q_FET_N_ENH__sym_2##2; DEVICE_TYPENAME: Q_FET_N_ENH_SOT23_1G1D1S-BSS13850V3500MOHM10V3500MOHM45V3500MOHM25V02A02A20V03W10V45V2B; DRAWING: @P2597_C02_LIB.P2597_C02(SCH_1):PAGE27; MAX_CURRENT: 0.2A; MAX_VOLTAGE: 50V; MAX_WATTAGE: 0.3W; NV_NAME: BSS138; NV_PN: 300-0156-000; PACK_TYPE: SOT23_1G1D1S; PATH: I262; PHYS_PAGE: 27; Q_G: [ ]@10V / [ ]@4.5V / [ ]@2.5V; ROT: 0; R_DS_ON: 3500mohm@10V / 3500mohm@4.5V / 3500mohm@2.5V; SEC: 1; VER: 2; V_BE_GS: 20V; XY: (-7550,4250)
Q44 = Q_FET_N_ENH#2: ASSEMBLY: CONN_POWER; CDS_LIB: discrete; CDS_PART_NAME: Q_FET_N_ENH_SOT23_1G1D1S-AO3402,30V,52MOHM@10V / 65MOHM@4.5V / -1000MOHM@2.5V,3.4A,15A,12V,1W,[ ]@10V / [ ]@4.5V / [ ]@2.5V,30A; CDS_PHYS_PART_NAME: Q_FET_N_ENH_SOT23_1G1D1S-AO3402,30V,52MOHM@10V / 65MOHM@4.5V / -1000MOHM@2.5V,3.4A,15A,12V,1W,[ ]@10V / [ ]@4.5V / [ ]@2.5V,30B; CDS_SEC: 1; CONTINUOUS_CURRENT: 3.4A; CaptureCellPackProp: Q_FET_N_ENH__sym_2##2; DEVICE_TYPENAME: Q_FET_N_ENH_SOT23_1G1D1S-AO340230V52MOHM10V65MOHM45V-1000MOHM25V34A15A12V1W10V45V25V30B; DRAWING: @P2597_C02_LIB.P2597_C02(SCH_1):PAGE27; MAX_CURRENT: 15A; MAX_VOLTAGE: 30V; MAX_WATTAGE: 1W; NV_NAME: AO3402; NV_PN: 300-0731-000; PACK_TYPE: SOT23_1G1D1S; PATH: I275; PHYS_PAGE: 27; Q_G: [ ]@10V / [ ]@4.5V / [ ]@2.5V; ROT: 0; R_DS_ON: 52mohm@10V / 65mohm@4.5V / -1000mohm@2.5V; SEC: 1; VER: 2; V_BE_GS: 12V; XY: (-7200,2400)
R264 = R: ASSEMBLY: CONN_POWER; CDS_LIB: discrete; CDS_PART_NAME: R_1206-0OHM,0.005 OHM,0.5W,195-1768-000; CDS_PHYS_PART_NAME: R_1206-0OHM,0.005 OHM,0.5W,195-1768-000-0OHM,195-1768-000; CDS_SEC: 1; DEVICE_TYPENAME: R_1206-0OHM0005OHM05W195-1768-000-0OHM195-1768-000; DRAWING: @P2597_C02_LIB.P2597_C02(SCH_1):PAGE27; MAX_WATTAGE: 0.5W; NV_PN: 195-1768-000; PATH: I189; PHYS_PAGE: 27; PLACEMENT_NOTE: CoLayout with LB13; ROT: 0; SEC: 1; SIGNAL_MODEL: nv_res; SKU: NO STUFF; TOL: 0.005 ohm; VER: 1; XY: (-5600,2750)
R265 = R_SENSE_4PIN: ASSEMBLY: CONN_POWER; CDS_LIB: discrete; CDS_PART_NAME: R_SENSE_4PIN_R_SENSE_4PIN-0.02OHM,1%,1W,[ ],215-0168-000; CDS_PHYS_PART_NAME: R_SENSE_4PIN_R_SENSE_4PIN-0.02OHM,1%,1W,[ ],215-0168-000-0.02OHM,215-0168-000; CDS_SEC: 1; DEVICE_TYPENAME: R_SENSE_4PIN_R_SENSE_4PIN-002OHM11W215-0168-000-002OHM215-0168-000; DRAWING: @P2597_C02_LIB.P2597_C02(SCH_1):PAGE27; MAX_WATTAGE: 1W; NV_PN: 215-0168-000; PATH: I4; PHYS_PAGE: 27; ROT: 2; SEC: 1; SIGNAL_MODEL: nv_res_sense_4p_noxnet; TEMP_COEF: [ ]; TOL: 1%; VER: 1; XY: (-3750,1150)
R272 = R#1: ASSEMBLY: CONN_POWER; CDS_LIB: discrete; CDS_PART_NAME: R_0402-100K,1 %,62.5MW,195-0005-000; CDS_PHYS_PART_NAME: R_0402-100K,1 %,62.5MW,195-0005-000-100K,195-0005-000; CDS_SEC: 1; CHIPS_PART_NAME: R; DEVICE_TYPENAME: R_0402-100K1625MW195-0005-000-100K195-0005-000; DRAWING: @P2597_C02_LIB.P2597_C02(SCH_1):PAGE27; MAX_WATTAGE: 62.5mW; NV_PN: 195-0005-000; PATH: I212; PHYS_PAGE: 27; ROT: 0; SEC: 1; SIGNAL_MODEL: nv_res; TOL: 1%; VER: 2; XY: (-4750,4400)
R273 = R: ASSEMBLY: CONN_POWER; CDS_LIB: discrete; CDS_PART_NAME: R_0402-10K,5 %,62.5MW,195-0486-000; CDS_PHYS_PART_NAME: R_0402-10K,5 %,62.5MW,195-0486-000-10K,195-0486-000; CDS_SEC: 1; DEVICE_TYPENAME: R_0402-10K5625MW195-0486-000-10K195-0486-000; DRAWING: @P2597_C02_LIB.P2597_C02(SCH_1):PAGE27; MAX_WATTAGE: 62.5mW; NV_PN: 195-0486-000; PATH: I211; PHYS_PAGE: 27; ROT: 0; SEC: 1; SIGNAL_MODEL: DEFAULT_RESISTOR_10000OHM_2_1; TOL: 5%; VER: 1; XY: (-4250,4600)
R274 = R#1: ASSEMBLY: CONN_POWER; CDS_LIB: discrete; CDS_PART_NAME: R_0402-47K,5 %,62.5MW,195-0599-000; CDS_PHYS_PART_NAME: R_0402-47K,5 %,62.5MW,195-0599-000-195-0599-000,47K; CDS_SEC: 1; CHIPS_PART_NAME: R; DEVICE_TYPENAME: R_0402-47K5625MW195-0599-000-195-0599-00047K; DRAWING: @P2597_C02_LIB.P2597_C02(SCH_1):PAGE27; MAX_WATTAGE: 62.5mW; NV_PN: 195-0599-000; PATH: I213; PHYS_PAGE: 27; ROT: 0; SEC: 1; SIGNAL_MODEL: nv_res; TOL: 5%; VER: 2; XY: (-4000,4400)
R285 = R: ASSEMBLY: ONOFF_CTRL_19VSS_CTRL_OPT_CMPLX; CDS_LIB: discrete; CDS_PART_NAME: R_0402-0OHM,0.05 OHM,62.5MW,195-2655-000; CDS_PHYS_PART_NAME: R_0402-0OHM,0.05 OHM,62.5MW,195-2655-000-0OHM,195-2655-000; CDS_SEC: 1; DEVICE_TYPENAME: R_0402-0OHM005OHM625MW195-2655-000-0OHM195-2655-000; DRAWING: @P2597_C02_LIB.P2597_C02(SCH_1):PAGE27; MAX_WATTAGE: 62.5mW; NV_PN: 195-2655-000; PATH: I298; PHYS_PAGE: 27; ROT: 0; SEC: 1; SIGNAL_MODEL: nv_res; TOL: 0.05 ohm; VER: 1; XY: (-9400,4200)
R286 = R#1: ASSEMBLY: ONOFF_CTRL_19VSS_CTRL_OPT_SMPL; CDS_LIB: discrete; CDS_PART_NAME: R_0402-100K,1 %,62.5MW,195-0005-000; CDS_PHYS_PART_NAME: R_0402-100K,1 %,62.5MW,195-0005-000-100K,195-0005-000; CDS_SEC: 1; CHIPS_PART_NAME: R; DEVICE_TYPENAME: R_0402-100K1625MW195-0005-000-100K195-0005-000; DRAWING: @P2597_C02_LIB.P2597_C02(SCH_1):PAGE27; MAX_WATTAGE: 62.5mW; NV_PN: 195-0005-000; PATH: I299; PHYS_PAGE: 27; ROT: 2; SEC: 1; SIGNAL_MODEL: nv_res; SKU: NO STUFF; TOL: 1%; VER: 2; XY: (-8800,1850)
R287 = R#1: ASSEMBLY: CONN_POWER_19VSS_AO_SMPL; CDS_LIB: discrete; CDS_PART_NAME: R_0402-10K,5 %,62.5MW,195-0486-000; CDS_PHYS_PART_NAME: R_0402-10K,5 %,62.5MW,195-0486-000-10K,195-0486-000; CDS_SEC: 1; CHIPS_PART_NAME: R; DEVICE_TYPENAME: R_0402-10K5625MW195-0486-000-10K195-0486-000; DRAWING: @P2597_C02_LIB.P2597_C02(SCH_1):PAGE27; MAX_WATTAGE: 62.5mW; NV_PN: 195-0486-000; PATH: I297; PHYS_PAGE: 27; ROT: 0; SEC: 1; SIGNAL_MODEL: DEFAULT_RESISTOR_10000OHM_2_1; SKU: NO STUFF; TOL: 5%; VER: 2; XY: (-7800,5300)
R382 = R#1: ASSEMBLY: CONN_POWER; CDS_LIB: discrete; CDS_PART_NAME: R_0402-10K,5 %,62.5MW,195-0486-000; CDS_PHYS_PART_NAME: R_0402-10K,5 %,62.5MW,195-0486-000-10K,195-0486-000; CDS_SEC: 1; CHIPS_PART_NAME: R; DEVICE_TYPENAME: R_0402-10K5625MW195-0486-000-10K195-0486-000; DRAWING: @P2597_C02_LIB.P2597_C02(SCH_1):PAGE27; MAX_WATTAGE: 62.5mW; NV_PN: 195-0486-000; PATH: I279; PHYS_PAGE: 27; ROT: 0; SEC: 1; SIGNAL_MODEL: DEFAULT_RESISTOR_10000OHM_2_1; TOL: 5%; VER: 2; XY: (-7500,2800)
R383 = R#1: ASSEMBLY: CONN_POWER19VSS_CTRL_PD_CMPLX; CDS_LIB: discrete; CDS_PART_NAME: R_0402-10K,5 %,62.5MW,195-0486-000; CDS_PHYS_PART_NAME: R_0402-10K,5 %,62.5MW,195-0486-000-10K,195-0486-000; CDS_SEC: 1; CHIPS_PART_NAME: R; DEVICE_TYPENAME: R_0402-10K5625MW195-0486-000-10K195-0486-000; DRAWING: @P2597_C02_LIB.P2597_C02(SCH_1):PAGE27; MAX_WATTAGE: 62.5mW; NV_PN: 195-0486-000; PATH: I264; PHYS_PAGE: 27; ROT: 0; SEC: 1; SIGNAL_MODEL: DEFAULT_RESISTOR_10000OHM_2_1; TOL: 5%; VER: 2; XY: (-7450,4700)
R384 = R#1: ASSEMBLY: ONOFF_CTRL_19VDRAIN_CMPLX; CDS_LIB: discrete; CDS_PART_NAME: R_0603-221OHM,1 %,0.1W,195-0818-000; CDS_PHYS_PART_NAME: R_0603-221OHM,1 %,0.1W,195-0818-000-195-0818-000,221OHM; CDS_SEC: 1; CHIPS_PART_NAME: R; DEVICE_TYPENAME: R_0603-221OHM101W195-0818-000-195-0818-000221OHM; DRAWING: @P2597_C02_LIB.P2597_C02(SCH_1):PAGE27; MAX_WATTAGE: 0.1W; NV_PN: 195-0818-000; PATH: I276; PHYS_PAGE: 27; ROT: 0; SEC: 1; SIGNAL_MODEL: nv_res; TOL: 1%; VER: 2; XY: (-7100,2900)
R501 = R#1: ASSEMBLY: CONN_POWER_19SS_CTRL_PU_CMPLX; CDS_LIB: discrete; CDS_PART_NAME: R_0402-10K,5 %,62.5MW,195-0486-000; CDS_PHYS_PART_NAME: R_0402-10K,5 %,62.5MW,195-0486-000-10K,195-0486-000; CDS_SEC: 1; CHIPS_PART_NAME: R; DEVICE_TYPENAME: R_0402-10K5625MW195-0486-000-10K195-0486-000; DRAWING: @P2597_C02_LIB.P2597_C02(SCH_1):PAGE27; MAX_WATTAGE: 62.5mW; NV_PN: 195-0486-000; PATH: I171; PHYS_PAGE: 27; ROT: 0; SEC: 1; SIGNAL_MODEL: DEFAULT_RESISTOR_10000OHM_2_1; TOL: 5%; VER: 2; XY: (-7450,5300)

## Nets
5V0_AO: R382.1 ; also on sheet 14 15
19V_INPUT: C176.1 LB12.1 LB13.1 LB14.1 Q30.5(D) R264.1 R265.4 R384.1
GND: C75.2 C77.2 C102.2 C166.2 C167.2 C168.2 C169.2 C174.2 C177.2 C178.2 C179.2 C182.2 C183.2 C184.2 C185.2 C186.2 C187.2 C188.2 C200.2 C202.2 C203.2 C204.2 C501.2 D13.1(A) D31.2(A) J25.2 J25.3 J25.4 J25.5 J25.6 Q31.2(S) Q42.2(S) Q43.2(S) Q44.2(S) R155.2 R172.2 R272.2 R274.2 R286.2 R287.1 R303.2 U11.4(GND) U11.9(TP) U32.2(GND) ; also on sheet 1 2 3 4 5 6 11 12 13 14 15 16 17 18 19 20 21 22 23 24 25 26 30
VDD_1V8: C102.1 R156.1 R157.1 R158.1 R302.1 U11.8(VCC) ; also on sheet 4 5 12 13 16 17 18 19 20 22 24 30
VDD_1V8_SENSE: C204.1 R302.2 R303.1 U32.5(SENSE)
VDD_5V0_IO_SYS: C202.1 R301.1 U32.6(VCC) ; also on sheet 4 5 6 11 12 16 17 18 20 22 26 30
VDD_5V_CT: C203.1 R301.2 U32.4(CT)
VDD_5V_RST_L: R304.1 U32.1(RST*)
VDD_19V_CON: J25.1 LB15.1 LB16.1 LB17.1 LB18.1
VDD_19V_IN: C174.1 C177.1 C178.1 C179.1 C237.1 C501.1 D13.3(C) LB15.2 LB16.2 LB17.2 LB18.2 Q30.1(S1) Q30.2(S2) Q30.3(S3) R501.1 ; also on sheet 15
VDD_MOD: C75.1 C77.1 C166.1 C167.1 C168.1 C169.1 C182.1 C183.1 C184.1 C185.1 C186.1 C187.1 C188.1 C200.1 LB12.2 LB13.2 LB14.2 R264.2 ; also on sheet 30
VDD_MUX: R265.1 ; also on sheet 4 6 17
VDD_MUX_N: R265.2 ; also on sheet 3
VDD_MUX_P: R265.3 ; also on sheet 3
VIN_DISCHARGE_D: Q44.3(D) R384.2
VIN_DISCHARGE_G: Q42.3(D) Q44.1(G) R382.2
VIN_PWR_BAD_C: C176.2 D31.1(C) R272.1 R273.1
VIN_PWR_BAD_CQ: Q31.1(G) R273.2 R274.1
VIN_PWR_BAD_L: Q31.3(D) ; also on sheet 4 6 30
BOARD_ID_A0: R155.1 R156.2 U11.1(A0)
BOARD_ID_WP: R172.1 U11.7(WP)
BRD_ID_A1: R157.2 U11.2(A1)
BRD_ID_A2: R158.2 U11.3(A2)
I2C_PM_CLK: TP20.1 U11.6(SCL) ; also on sheet 12 16 18 30
I2C_PM_DAT: TP19.1 U11.5(SDA) ; also on sheet 12 16 18 30
MOD_VIN_EN: R285.1 ; also on sheet 14 15
MOD_VIN_EN_D: Q43.3(D) R383.2
MOD_VIN_EN_G: C237.2 Q30.4(G) R287.2 R383.1 R501.2
MOD_VIN_EN_OPT: Q42.1(G) Q43.1(G) R285.2 R286.1
RESET_OUT_L: R304.2 ; also on sheet 5 12 18 30
SNN_VDD_5V_MR_L: U32.3(MR*)

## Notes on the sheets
sheet 7
- A
- B
- C
- D
- E
- F
- G
- H
- 19V Jack
- DC JACK
- 1
- 1
- PLUG 5.5 0D, 2.5 ID
- 2
- 2
- 3
- 3
- PCB CO-LAYOUT
- To Compute Module
- MAX CURRENT: 8A
- 4
- 4
- To IO board
- 5
- 5
- NVIDIA CORPORATION
- 2701 SAN TOMAS EXPRESSWAY
- ASSEMBLY
- <ASSEMBLY_DESCRIPTION>
- SANTA CLARA, CA 95050, USA
- PAGE DETAIL
- DC Jack
- NV_PN
- 600-82597-BASE-900
- ALL NVIDIA DESIGN SPECIFICATIONS, REFERENCE SPECIFICATIONS, REFERENCE BOARDS, FILES, DRAWINGS, DIAGNOSTICS, LISTS AND OTHER DOCUMENTS OR INFORMATION (TOGETHER AND SEPARATELY, 'MATERIALS') ARE BEING PROVIDED 'AS IS'. THE MATERIALS MAY
- CONTAIN KNOWN AND UNKNOWN VIOLATIONS OR DEVIATIONS OF INDUSTRY STANDARDS AND SPECIFICATIONS. NVIDIA MAKES NO WARRANTIES, EXPRESSED, IMPLIED, STATUTORY OR OTHERWISE WITH RESPECT TO THE MATERIALS OR OTHERWISE, AND EXPRESSLY DISCLAIMS ALL
- PCB REV
- P2597-C02
- PAGE
- 27 OF 34
- IMPLIED WARRANTIES INCLUDING, WITHOUT LIMITATION, THE WARRANTIES OF DESIGN, OF NONINFRINGEMENT, MERCHANTABILITY OR FITNESS FOR A PARTICULAR PURPOSE, OR ARISING FROM A COURSE OF DEALING, TRADE USAGE, TRADE PRACTICE, OR INDUSTRY STANDARDS.
- BOM REV
- A
- DATE
- 23-OCT-2017
- A
- B
- C
- D
- E
- F
- G
- H
sheet 8
- A
- B
- C
- D
- E
- F
- G
- H
- BLANK
- 1
- 1
- 2
- 2
- 3
- 3
- 4
- 4
- 5
- 5
- NVIDIA CORPORATION
- 2701 SAN TOMAS EXPRESSWAY
- ASSEMBLY
- <ASSEMBLY_DESCRIPTION>
- SANTA CLARA, CA 95050, USA
- PAGE DETAIL
- BLANK
- NV_PN
- 600-82597-BASE-900
- ALL NVIDIA DESIGN SPECIFICATIONS, REFERENCE SPECIFICATIONS, REFERENCE BOARDS, FILES, DRAWINGS, DIAGNOSTICS, LISTS AND OTHER DOCUMENTS OR INFORMATION (TOGETHER AND SEPARATELY, 'MATERIALS') ARE BEING PROVIDED 'AS IS'. THE MATERIALS MAY
- CONTAIN KNOWN AND UNKNOWN VIOLATIONS OR DEVIATIONS OF INDUSTRY STANDARDS AND SPECIFICATIONS. NVIDIA MAKES NO WARRANTIES, EXPRESSED, IMPLIED, STATUTORY OR OTHERWISE WITH RESPECT TO THE MATERIALS OR OTHERWISE, AND EXPRESSLY DISCLAIMS ALL
- PCB REV
- P2597-C02
- PAGE
- 26 OF 34
- IMPLIED WARRANTIES INCLUDING, WITHOUT LIMITATION, THE WARRANTIES OF DESIGN, OF NONINFRINGEMENT, MERCHANTABILITY OR FITNESS FOR A PARTICULAR PURPOSE, OR ARISING FROM A COURSE OF DEALING, TRADE USAGE, TRADE PRACTICE, OR INDUSTRY STANDARDS.
- BOM REV
- A
- DATE
- 23-OCT-2017
- A
- B
- C
- D
- E
- F
- G
- H
sheet 9
- A
- B
- C
- D
- E
- F
- G
- H
- 1
- 1
- 2
- 2
- VREF = 0.405V
- 3
- 3
- 4
- 4
- 5
- 5
- NVIDIA CORPORATION
- 2701 SAN TOMAS EXPRESSWAY
- ASSEMBLY
- <ASSEMBLY_DESCRIPTION>
- SANTA CLARA, CA 95050, USA
- PAGE DETAIL
- Supervisor
- NV_PN
- 600-82597-BASE-900
- ALL NVIDIA DESIGN SPECIFICATIONS, REFERENCE SPECIFICATIONS, REFERENCE BOARDS, FILES, DRAWINGS, DIAGNOSTICS, LISTS AND OTHER DOCUMENTS OR INFORMATION (TOGETHER AND SEPARATELY, 'MATERIALS') ARE BEING PROVIDED 'AS IS'. THE MATERIALS MAY
- CONTAIN KNOWN AND UNKNOWN VIOLATIONS OR DEVIATIONS OF INDUSTRY STANDARDS AND SPECIFICATIONS. NVIDIA MAKES NO WARRANTIES, EXPRESSED, IMPLIED, STATUTORY OR OTHERWISE WITH RESPECT TO THE MATERIALS OR OTHERWISE, AND EXPRESSLY DISCLAIMS ALL
- PCB REV
- P2597-C02
- PAGE
- 25 OF 34
- IMPLIED WARRANTIES INCLUDING, WITHOUT LIMITATION, THE WARRANTIES OF DESIGN, OF NONINFRINGEMENT, MERCHANTABILITY OR FITNESS FOR A PARTICULAR PURPOSE, OR ARISING FROM A COURSE OF DEALING, TRADE USAGE, TRADE PRACTICE, OR INDUSTRY STANDARDS.
- BOM REV
- A
- DATE
- 23-OCT-2017
- A
- B
- C
- D
- E
- F
- G
- H
sheet 10
- A
- B
- C
- D
- E
- F
- G
- H
- 1
- 1
- 2
- 2
- Carrier board config
- NS
- 7'b1010xxx
- 3
- 7'b1010111 = 7'h57
- 3
- 4
- 4
- 5
- 5
- NVIDIA CORPORATION
- 2701 SAN TOMAS EXPRESSWAY
- ASSEMBLY
- <ASSEMBLY_DESCRIPTION>
- SANTA CLARA, CA 95050, USA
- PAGE DETAIL
- EEPROM
- NV_PN
- 600-82597-BASE-900
- ALL NVIDIA DESIGN SPECIFICATIONS, REFERENCE SPECIFICATIONS, REFERENCE BOARDS, FILES, DRAWINGS, DIAGNOSTICS, LISTS AND OTHER DOCUMENTS OR INFORMATION (TOGETHER AND SEPARATELY, 'MATERIALS') ARE BEING PROVIDED 'AS IS'. THE MATERIALS MAY
- CONTAIN KNOWN AND UNKNOWN VIOLATIONS OR DEVIATIONS OF INDUSTRY STANDARDS AND SPECIFICATIONS. NVIDIA MAKES NO WARRANTIES, EXPRESSED, IMPLIED, STATUTORY OR OTHERWISE WITH RESPECT TO THE MATERIALS OR OTHERWISE, AND EXPRESSLY DISCLAIMS ALL
- PCB REV
- P2597-C02
- PAGE
- 24 OF 34
- IMPLIED WARRANTIES INCLUDING, WITHOUT LIMITATION, THE WARRANTIES OF DESIGN, OF NONINFRINGEMENT, MERCHANTABILITY OR FITNESS FOR A PARTICULAR PURPOSE, OR ARISING FROM A COURSE OF DEALING, TRADE USAGE, TRADE PRACTICE, OR INDUSTRY STANDARDS.
- BOM REV
- A
- DATE
- 23-OCT-2017
- A
- B
- C
- D
- E
- F
- G
- H
